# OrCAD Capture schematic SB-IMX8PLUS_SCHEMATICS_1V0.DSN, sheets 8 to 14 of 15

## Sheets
8 08. LVDS LCD: size A3; title: SB-iMX8PLUS   08. LVDS LCD
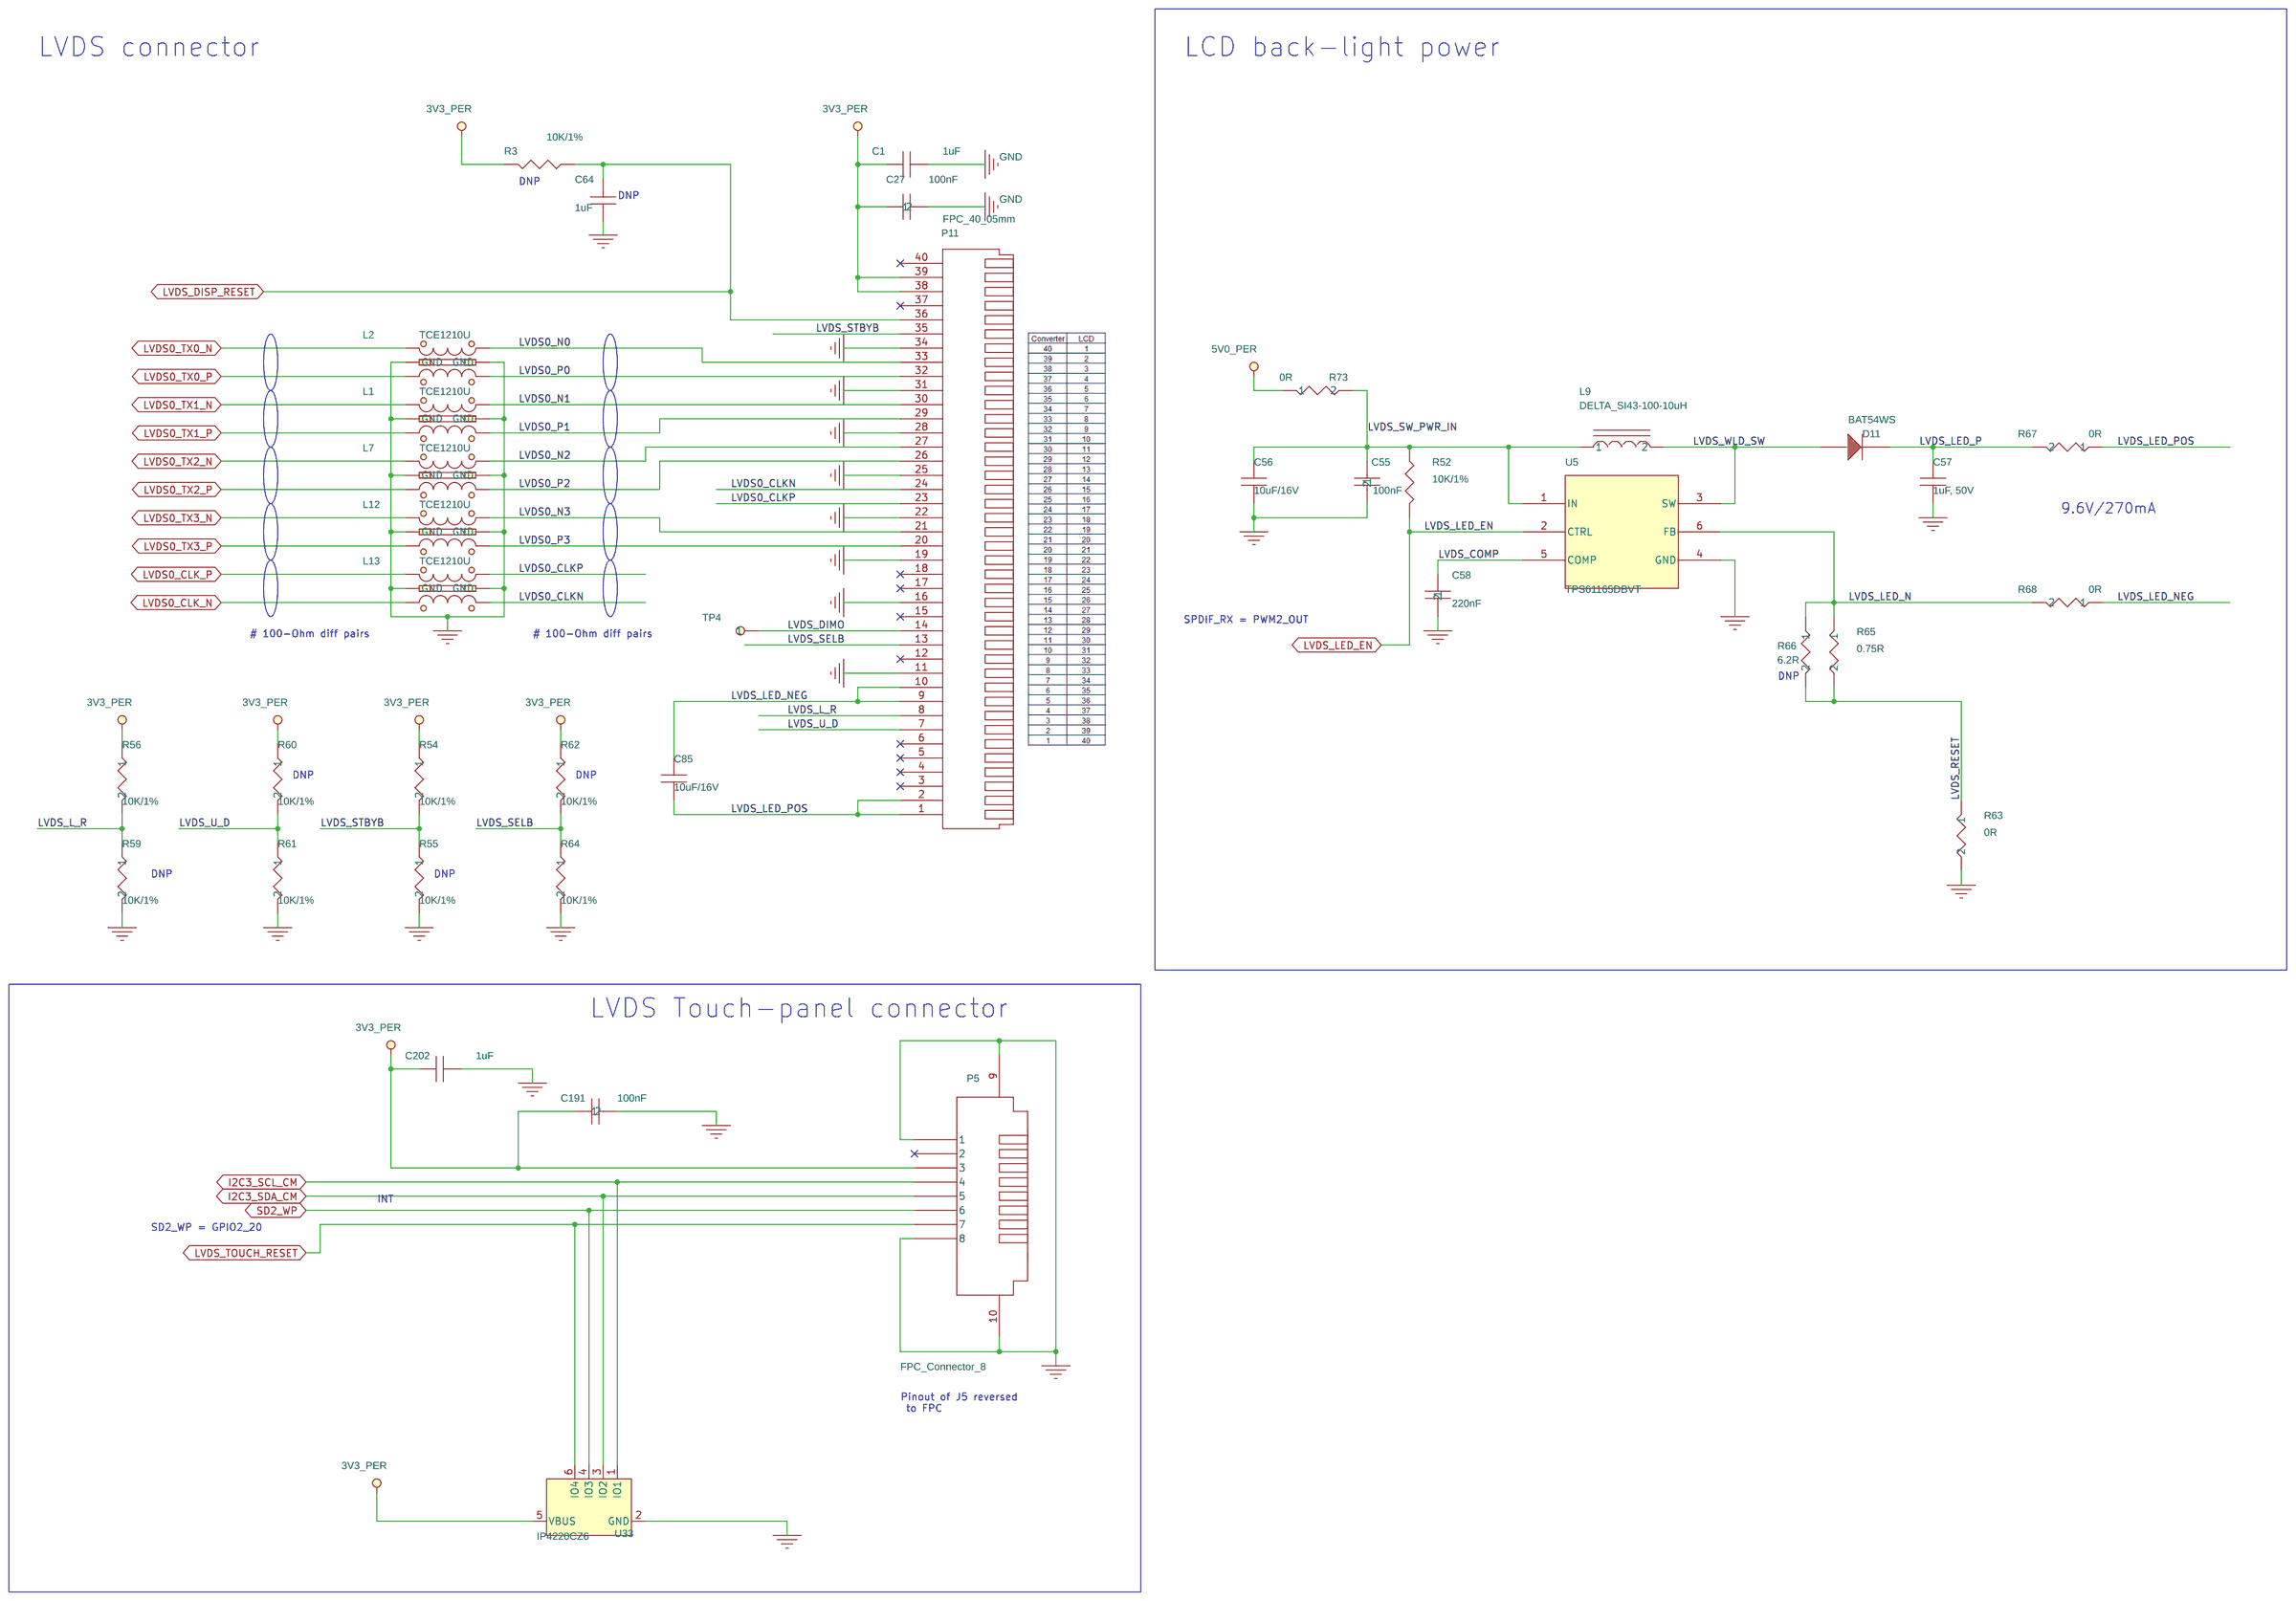
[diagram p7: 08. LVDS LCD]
9 09. HDMI, eARC: size B; title: SB-iMX8PLUS   09. HDMI, eARC
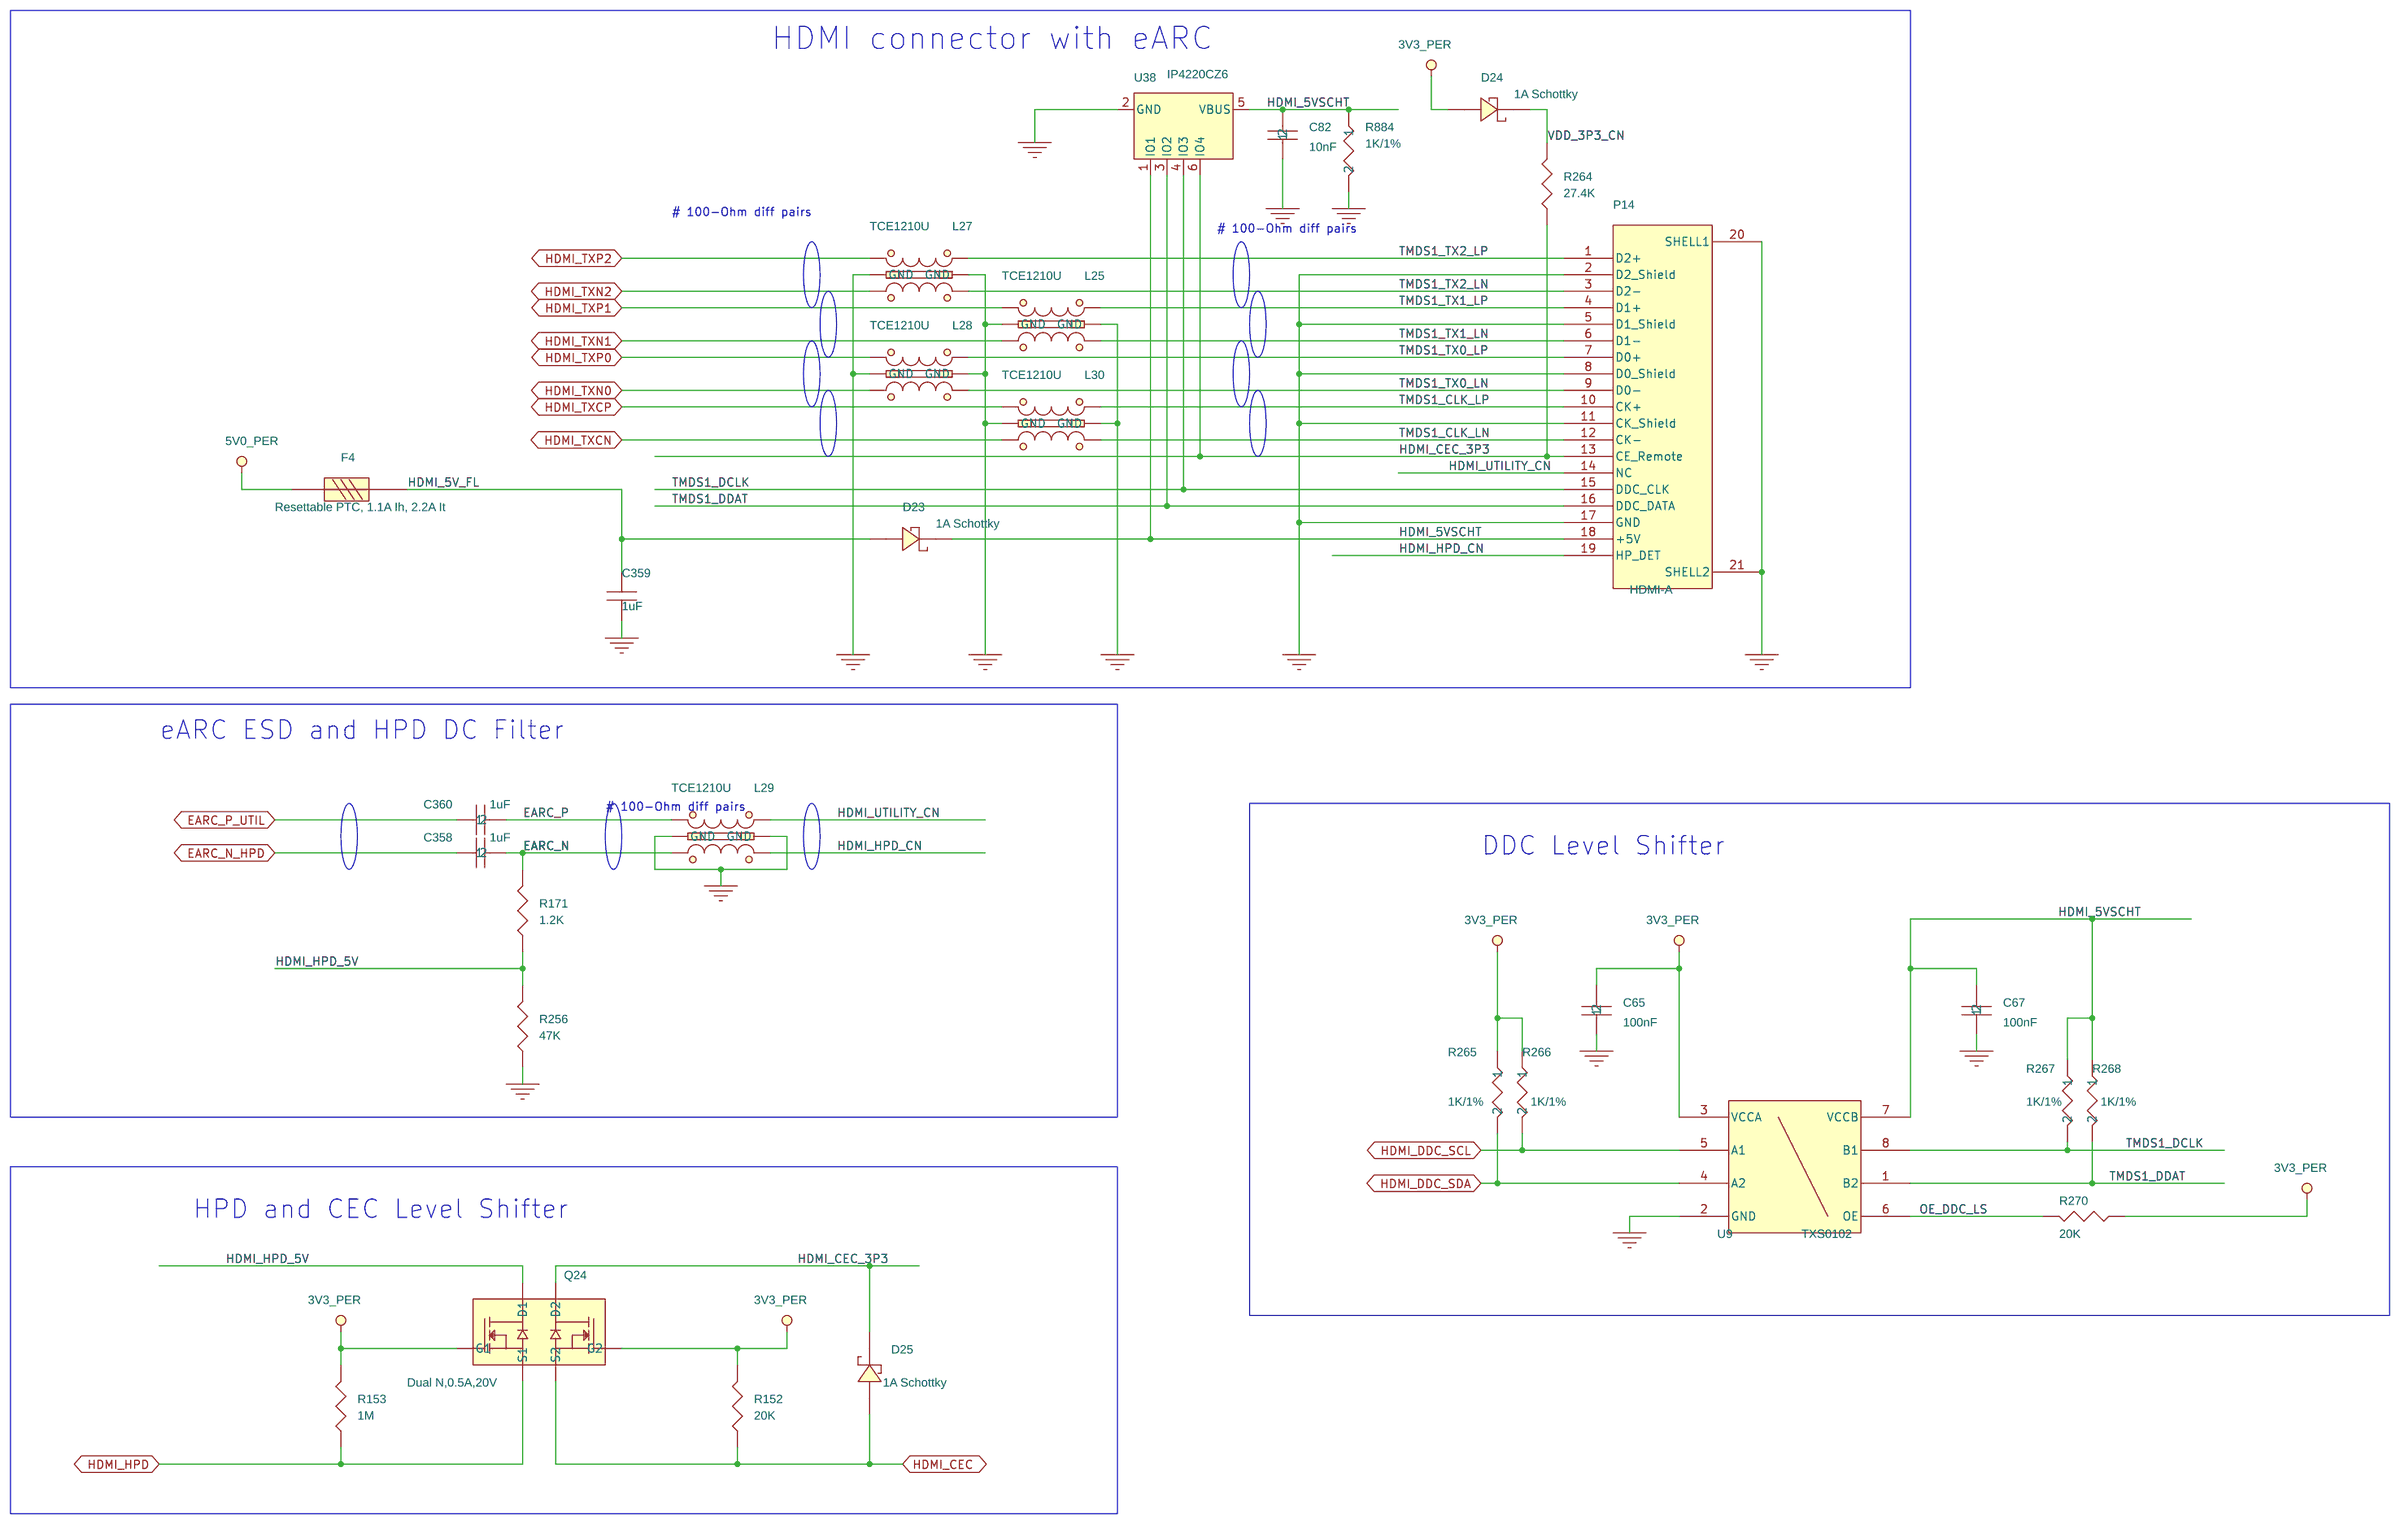
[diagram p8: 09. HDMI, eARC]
10 10. MIPI-CSI1 Connectors_A: size A3; title: SB-iMX8PLUS    10. MIPI-CSI1 Connectors
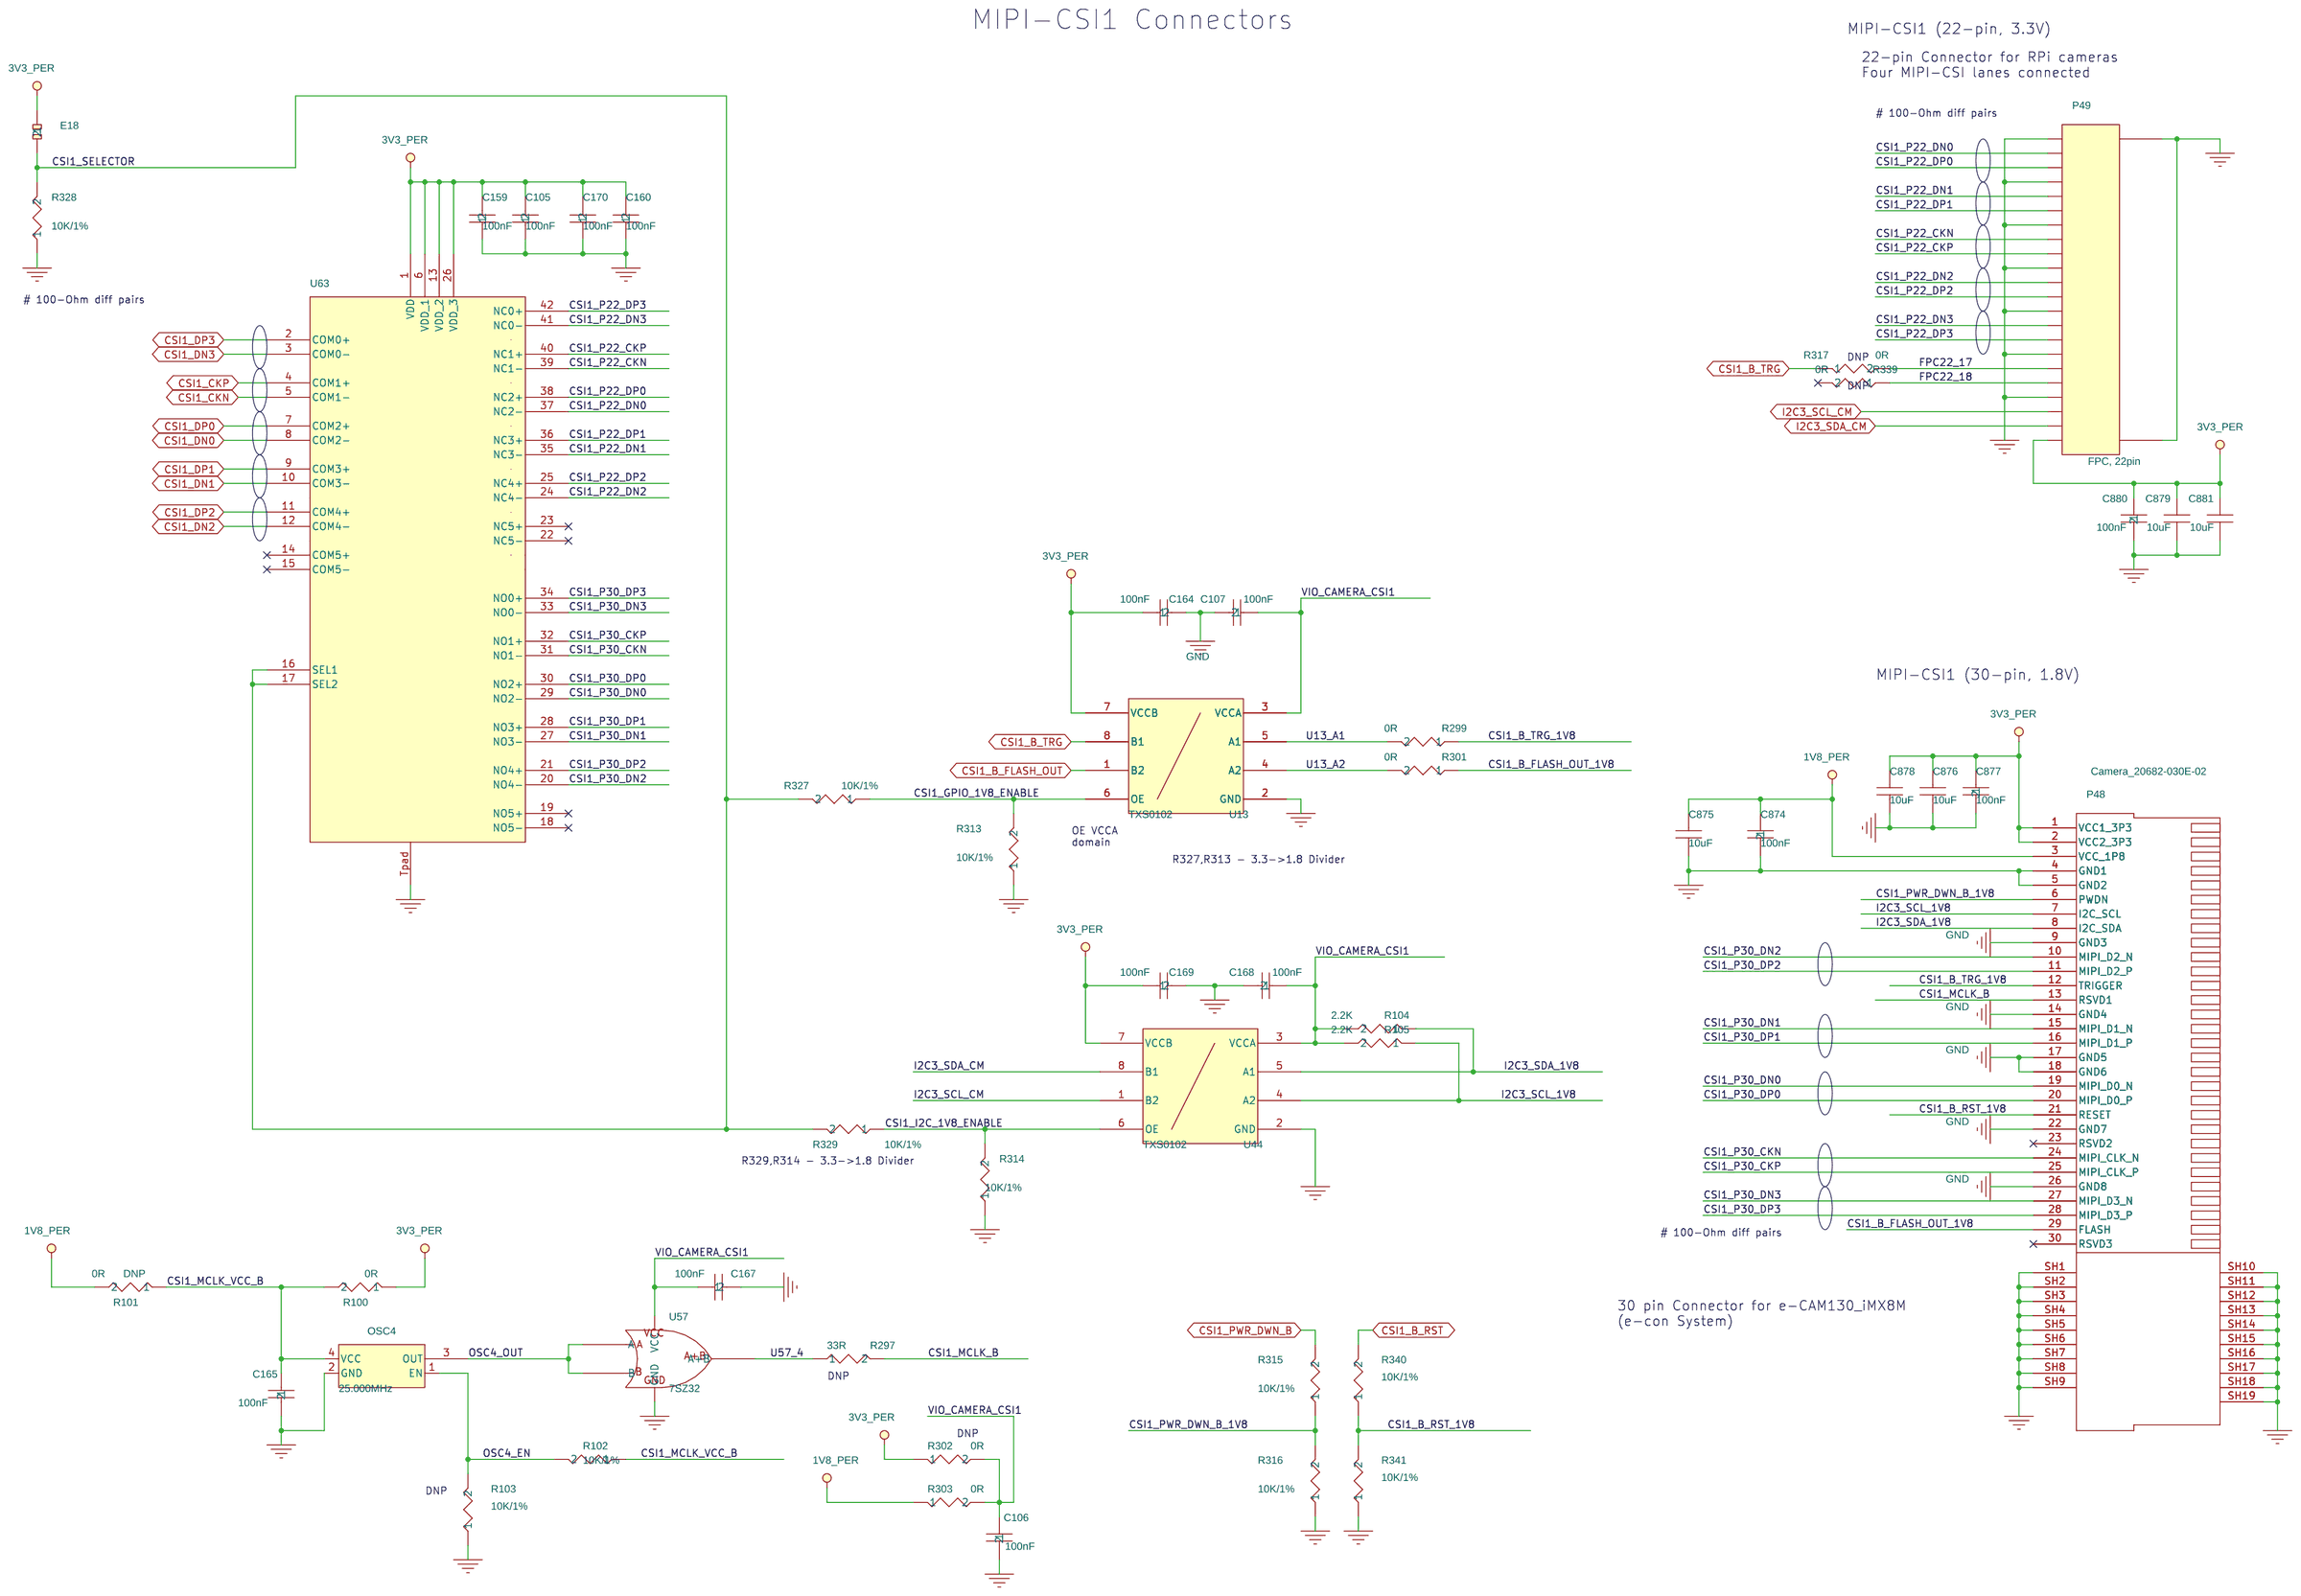
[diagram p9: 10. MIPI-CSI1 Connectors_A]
11 11. MIPI-CSI2 Connectors_B: size A3; title: SB-iMX8PLUS    11. MIPI-CSI2 Connectors
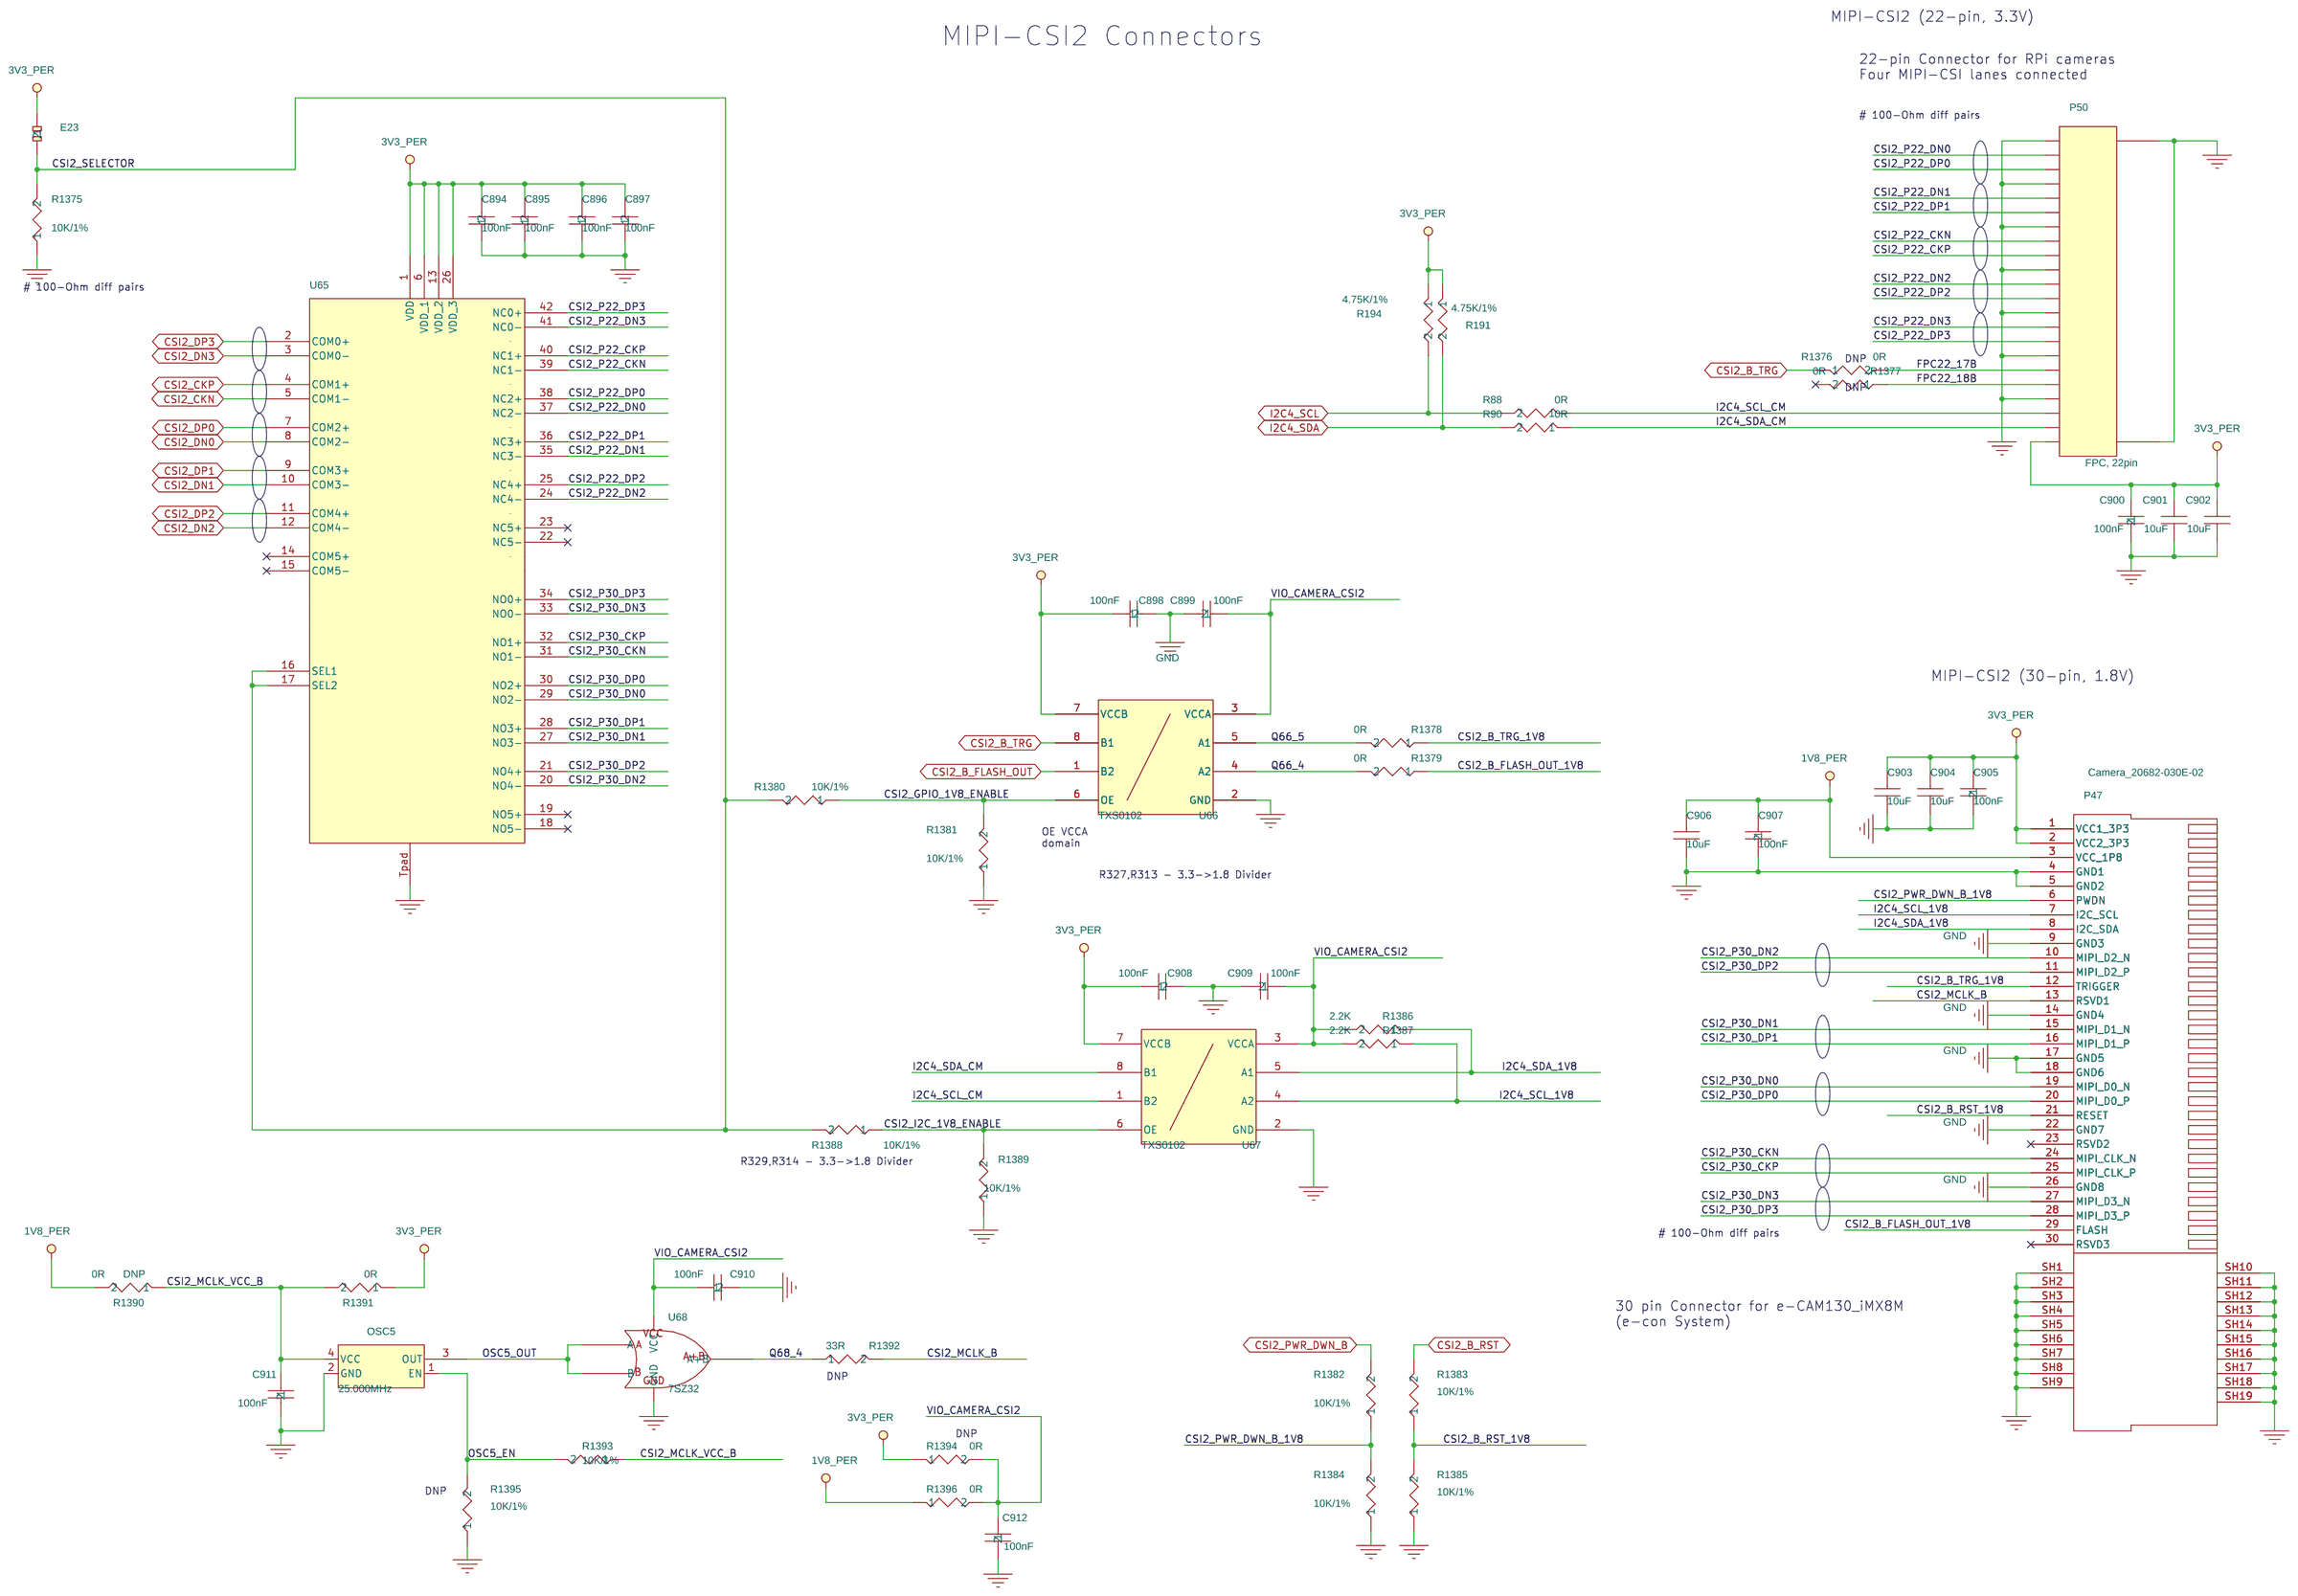
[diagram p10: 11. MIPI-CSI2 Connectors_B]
12 12. PCIe: size B; title: SB-iMX8PLUS    12. PCIe
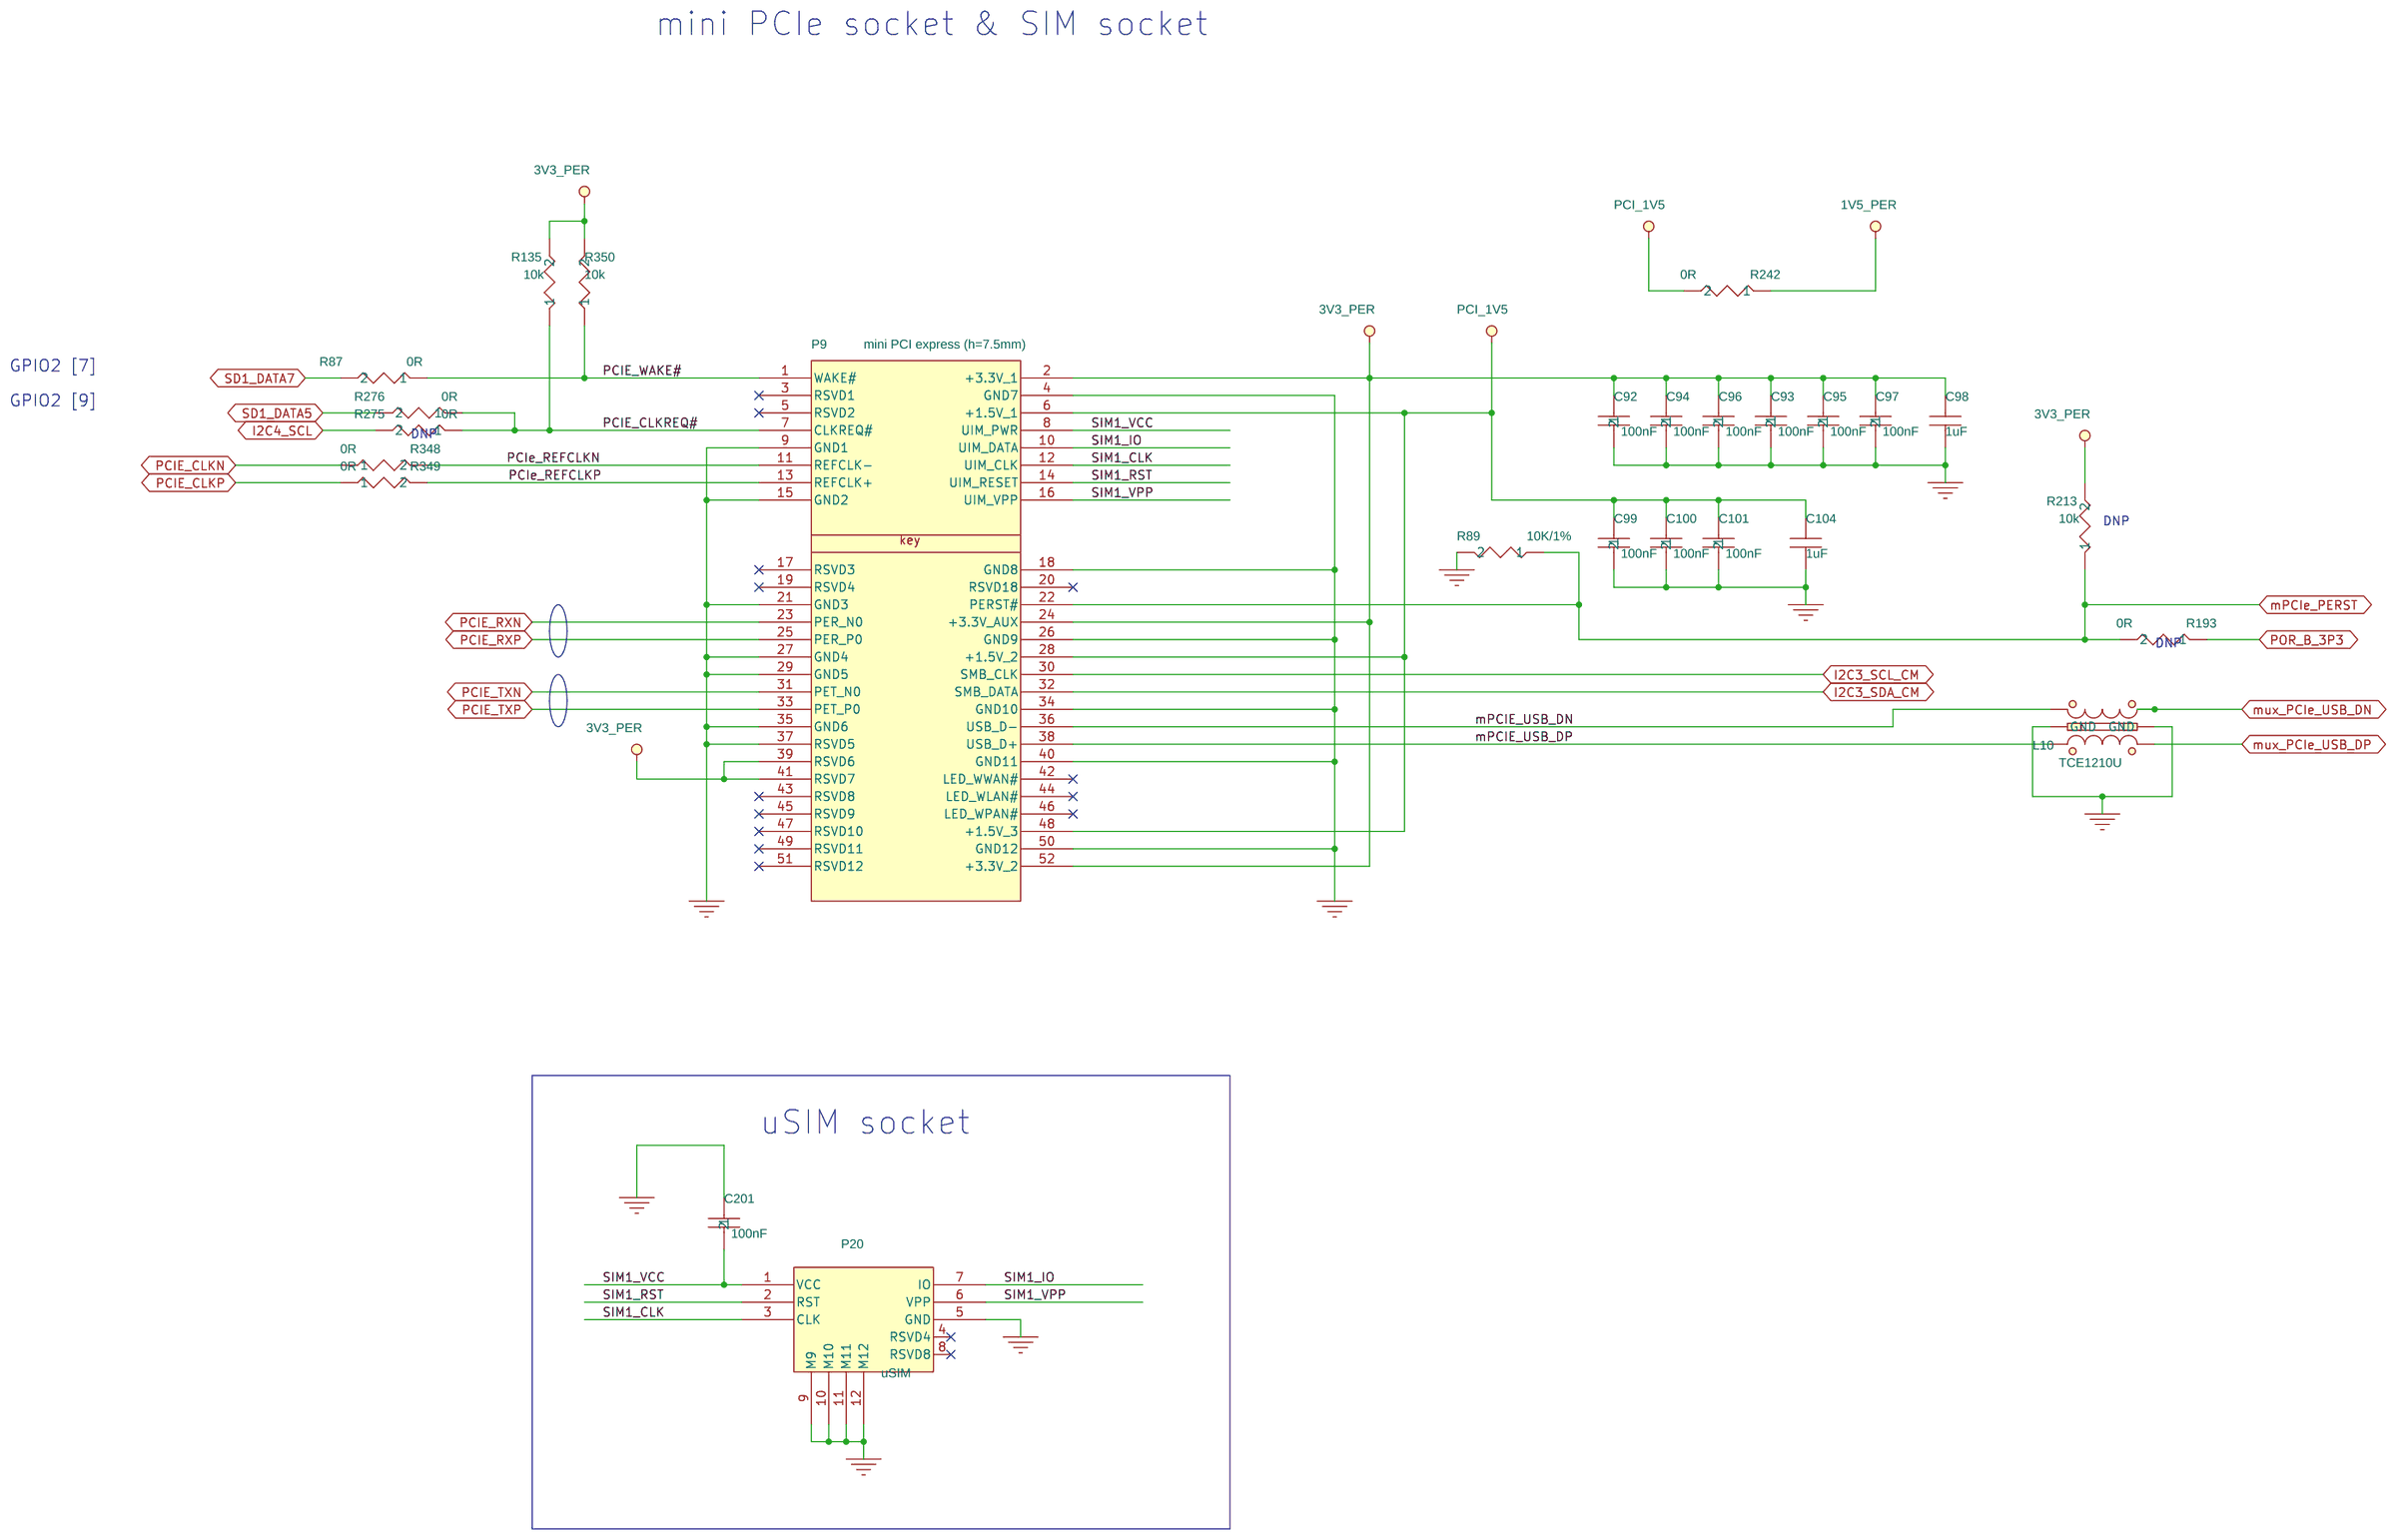
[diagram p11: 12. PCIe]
13 13. Power: size A3; title: SB-iMX8PLUS    13. POWER
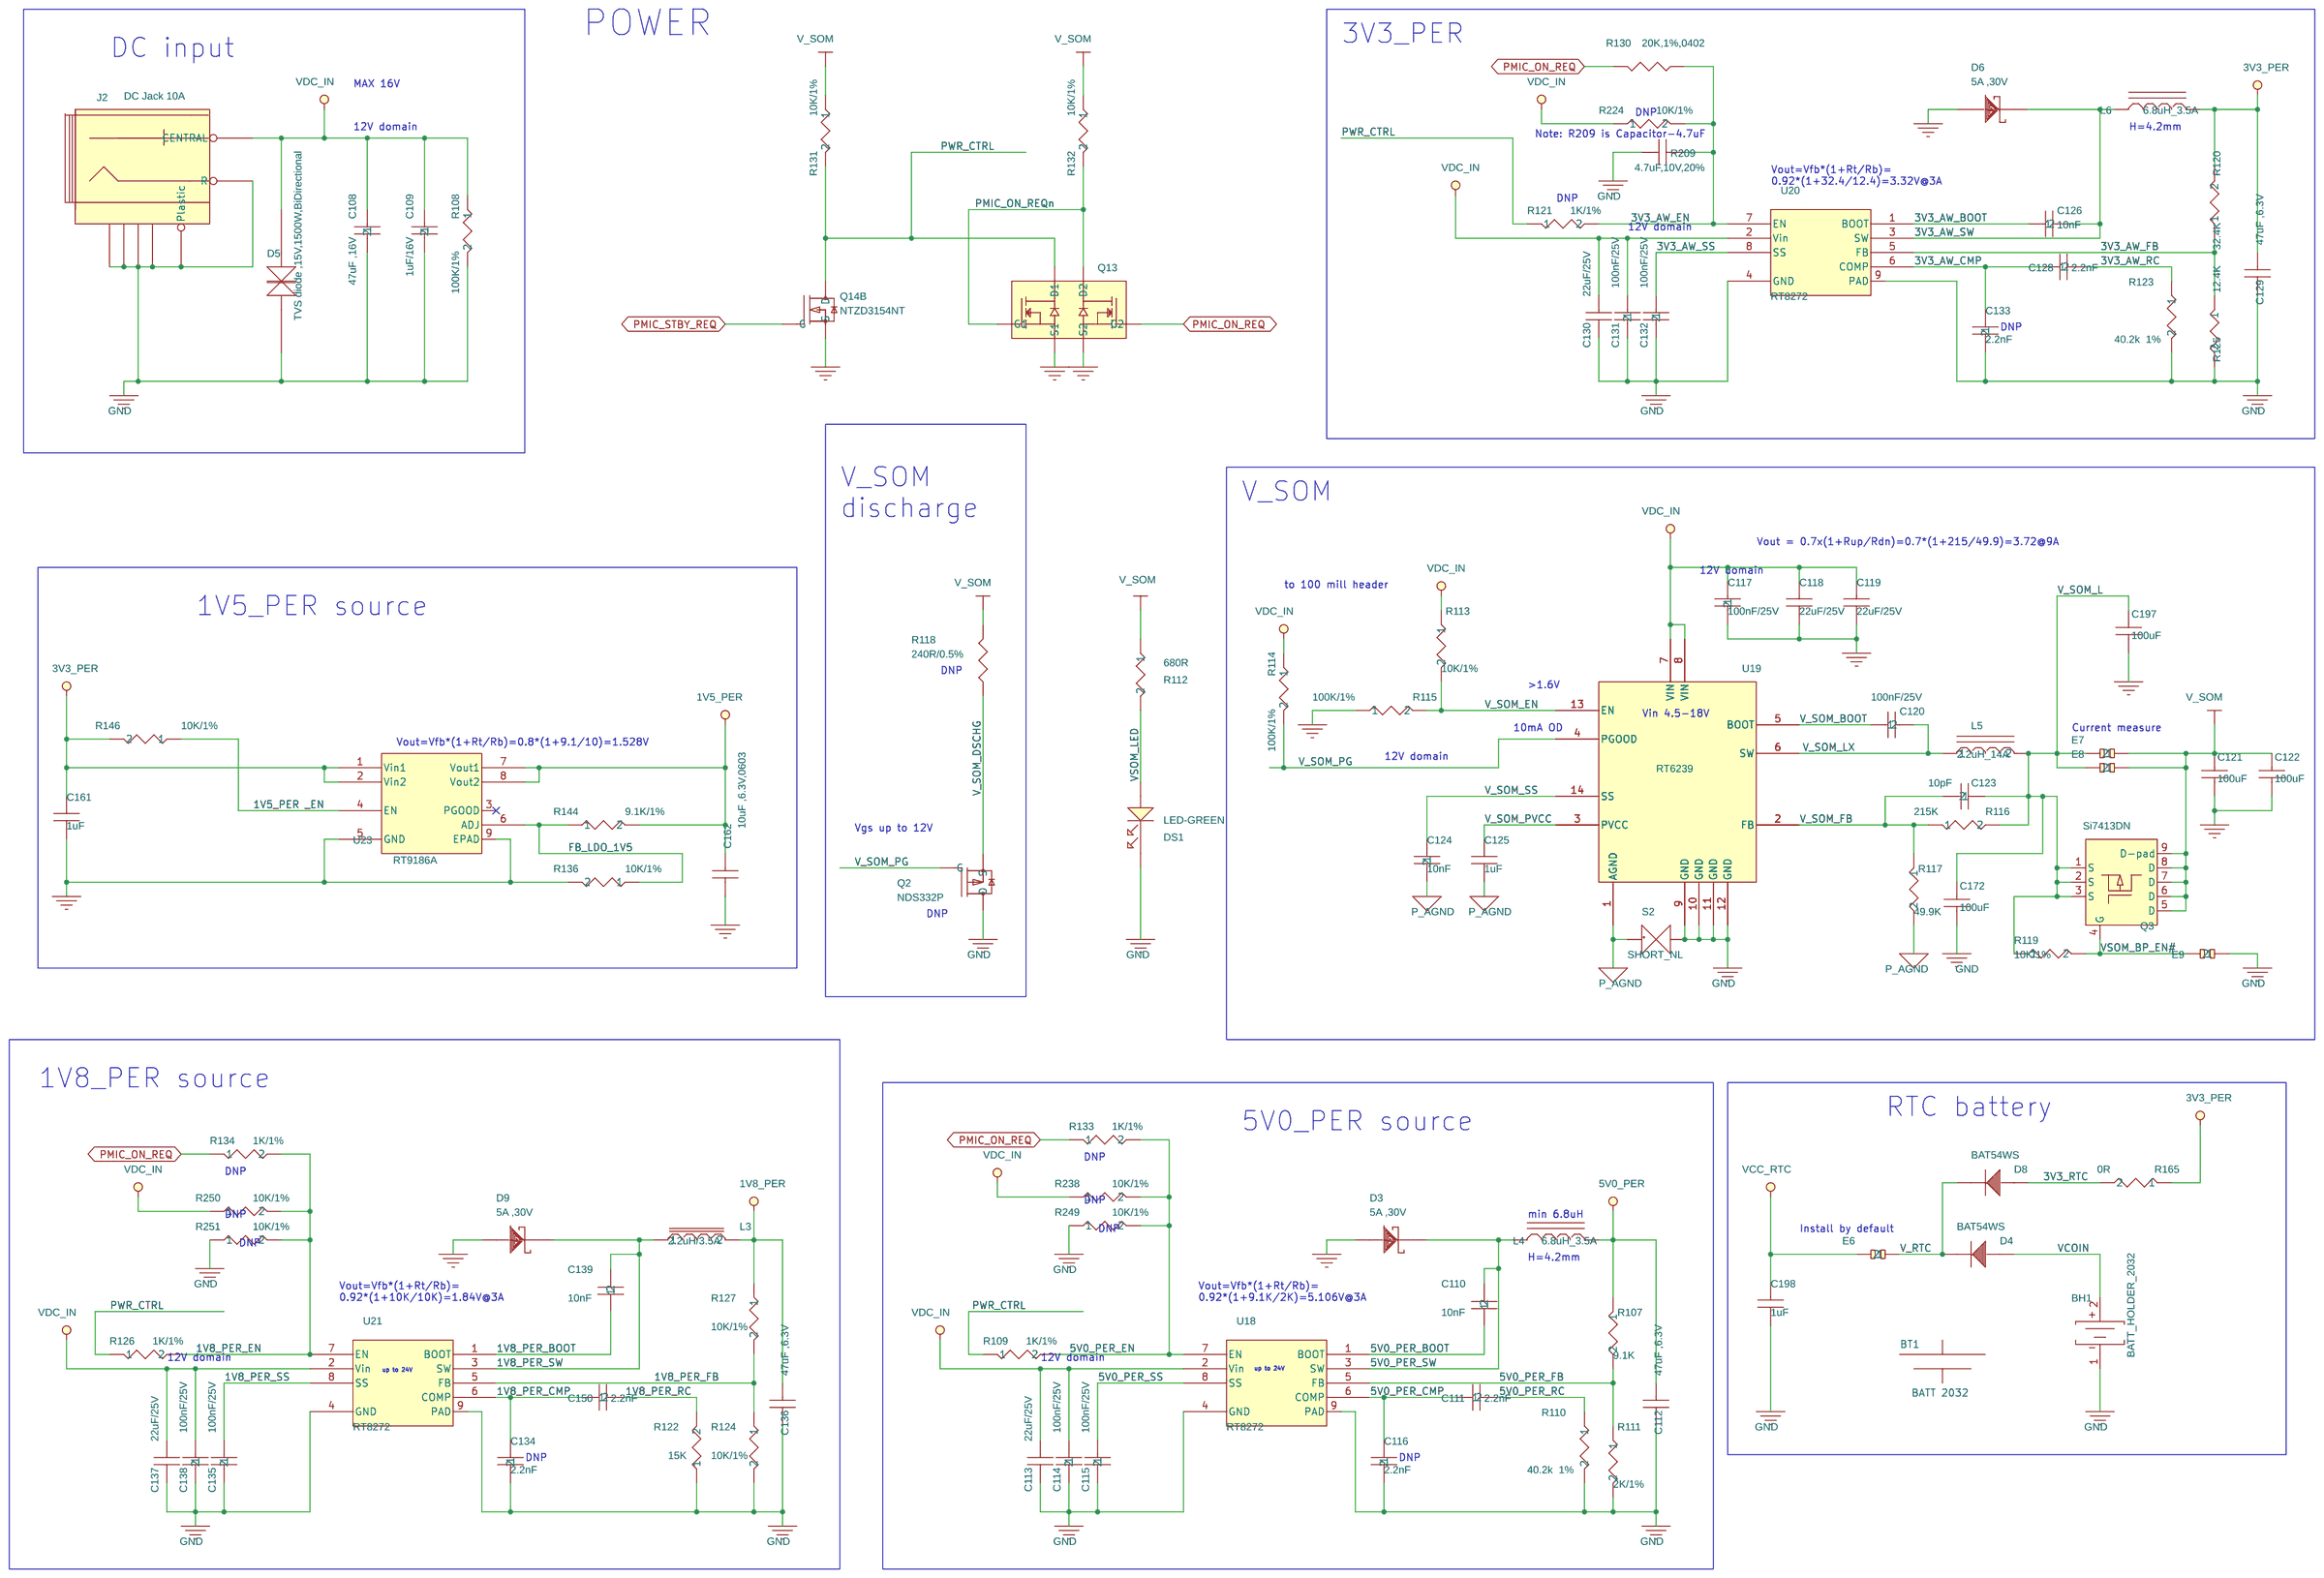
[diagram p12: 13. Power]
14 14. UART, RS232, SD, EEPROM: size A2; title: SB-iMX8PLUS      14. UART, RS232, SD Slot, EEPROM,GPIO
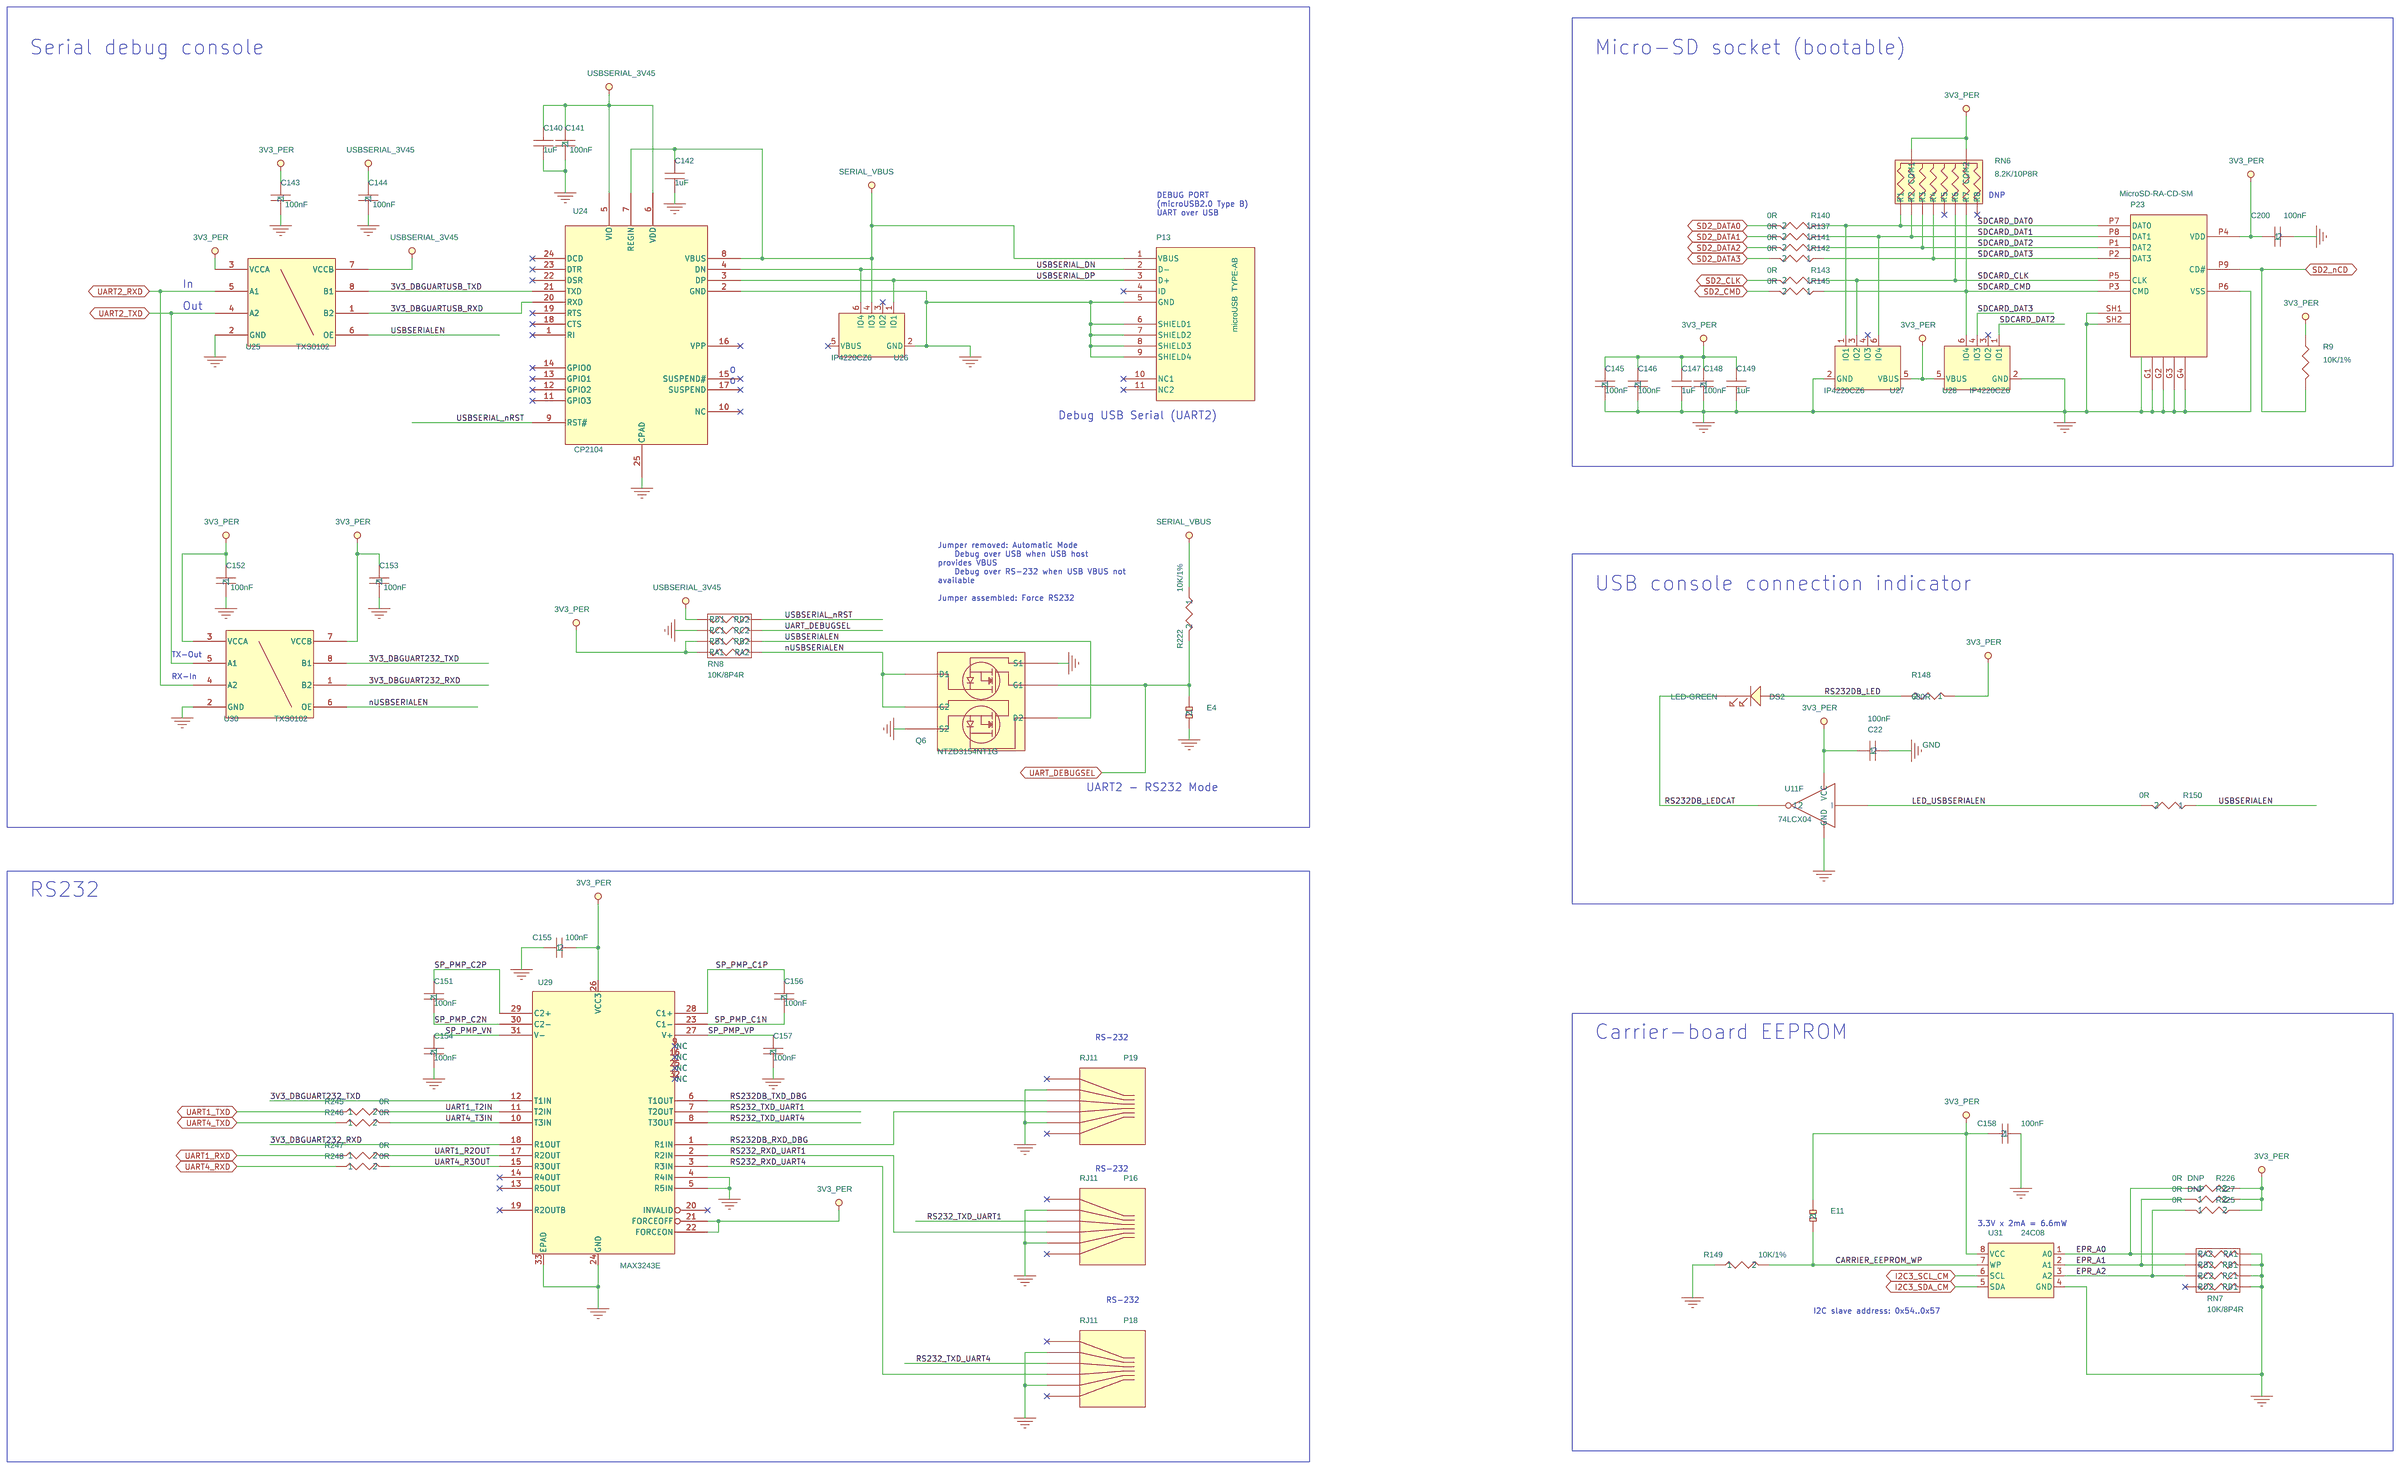
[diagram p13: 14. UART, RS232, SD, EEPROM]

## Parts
sheet 06. JTAG, CAN, GPIO Exp., Misc.
Q14  NTZD3154NT  [SOT-563-6]  (sections A,B)
sheet 08. LVDS LCD
C1  1uF  [RC0402]
C27  100nF  [RC0402]
C55  100nF  [RC0402]
C56  10uF/16V  [RC0603]
C57  1uF, 50V  [RC0603]
C58  220nF  [RC0402]
C64  1uF  [RC0402]
C85  10uF/16V  [RC0603]
C191  100nF  [RC0402]
C202  1uF  [RC0402]
D11  BAT54WS  [SOD-323]
L1  TCE1210U  [EMI1012-ESD]
L2  TCE1210U  [EMI1012-ESD]
L7  TCE1210U  [EMI1012-ESD]
L9  DELTA_SI43-100-10uH  [IND4x4x2_5]
L12  TCE1210U  [EMI1012-ESD]
L13  TCE1210U  [EMI1012-ESD]
P5  FPC_Connector_8  [FPC_8]
P11  FPC_40_05mm  [FPC05SM40-1]
R3  10K/1%  [RC0402]
R52  10K/1%  [RC0402]
R54  10K/1%  [RC0402]
R55  10K/1%  [RC0402]
R56  10K/1%  [RC0402]
R59  10K/1%  [RC0402]
R60  10K/1%  [RC0402]
R61  10K/1%  [RC0402]
R62  10K/1%  [RC0402]
R63  0R  [RC0402]
R64  10K/1%  [RC0402]
R65  0.75R  [RC0402]
R66  6.2R  [RC0402]
R67  0R  [RC1206]
R68  0R  [RC1206]
R73  0R  [RC1206]
TP4  TESTPOINT  [TESTPOINT]
U5  TPS61165DBVT  [SOT23-6]
U33  IP4220CZ6  [SOT23-6L]
sheet 09. HDMI, eARC
C65  100nF  [RC0402]
C67  100nF  [RC0402]
C82  10nF  [RC0402]
C358  1uF  [RC0402]
C359  1uF  [RC0402]
C360  1uF  [RC0402]
D23  1A Schottky  [SOD-123]
D24  1A Schottky  [SOD-123]
D25  1A Schottky  [SOD-123]
F4  Resettable PTC, 1.1A Ih, 2.2A It  [FUSE-1206]
L25  TCE1210U  [EMI1012-ESD]
L27  TCE1210U  [EMI1012-ESD]
L28  TCE1210U  [EMI1012-ESD]
L29  TCE1210U  [EMI1012-ESD]
L30  TCE1210U  [EMI1012-ESD]
P14  HDMI-A  [SMT(HDMI-A)]
Q24  Dual N,0.5A,20V  [SOT-563-6]
R152  20K  [RC0402]
R153  1M  [RC0402]
R171  1.2K  [RC0402]
R256  47K  [RC0402]
R264  27.4K  [RC0402]
R265  1K/1%  [RC0402]
R266  1K/1%  [RC0402]
R267  1K/1%  [RC0402]
R268  1K/1%  [RC0402]
R270  20K  [RC0402]
R884  1K/1%  [RC0402]
U9  TXS0102  [MO-187DA-8]
U38  IP4220CZ6  [SOT23-6L]
sheet 10. MIPI-CSI1 Connectors_A
C105  100nF  [RC0402]
C106  100nF  [RC0402]
C107  100nF  [RC0402]
C159  100nF  [RC0402]
C160  100nF  [RC0402]
C164  100nF  [RC0402]
C165  100nF  [RC0402]
C167  100nF  [RC0402]
C168  100nF  [RC0402]
C169  100nF  [RC0402]
C170  100nF  [RC0402]
C874  100nF  [RC0402]
C875  10uF  [RC0603]
C876  10uF  [RC0603]
C877  100nF  [RC0402]
C878  10uF  [RC0603]
C879  10uF  [RC0603]
C880  100nF  [RC0402]
C881  10uF  [RC0603]
E18  HDR1X2  [1X2THHDR]
OSC4  25.000MHz  [OSC3225]
P48  Camera_20682-030E-02  [CON30]
P49  FPC, 22pin  [FPC05SM22]
R100  0R  [RC0402]
R101  0R  [RC0402]
R102  10K/1%  [RC0402]
R103  10K/1%  [RC0402]
R104  2.2K  [RC0402]
R105  2.2K  [RC0402]
R297  33R  [RC0402]
R299  0R  [RC0402]
R301  0R  [RC0402]
R302  0R  [RC0402]
R303  0R  [RC0402]
R313  10K/1%  [RC0402]
R314  10K/1%  [RC0402]
R315  10K/1%  [RC0402]
R316  10K/1%  [RC0402]
R317  0R  [RC0402]
R327  10K/1%  [RC0402]
R328  10K/1%  [RC0402]
R329  10K/1%  [RC0402]
R339  0R  [RC0402]
R340  10K/1%  [RC0402]
R341  10K/1%  [RC0402]
U13  TXS0102  [MO-187DA-8]
U44  TXS0102  [MO-187DA-8]
U57  7SZ32  [SC70]
U63  Value  [21-0181B_T423590M-1_MXM]
sheet 11. MIPI-CSI2 Connectors_B
C894  100nF  [RC0402]
C895  100nF  [RC0402]
C896  100nF  [RC0402]
C897  100nF  [RC0402]
C898  100nF  [RC0402]
C899  100nF  [RC0402]
C900  100nF  [RC0402]
C901  10uF  [RC0603]
C902  10uF  [RC0603]
C903  10uF  [RC0603]
C904  10uF  [RC0603]
C905  100nF  [RC0402]
C906  10uF  [RC0603]
C907  100nF  [RC0402]
C908  100nF  [RC0402]
C909  100nF  [RC0402]
C910  100nF  [RC0402]
C911  100nF  [RC0402]
C912  100nF  [RC0402]
E23  HDR1X2  [1X2THHDR]
OSC5  25.000MHz  [OSC3225]
P47  Camera_20682-030E-02  [CON30]
P50  FPC, 22pin  [FPC05SM22]
R88  0R  [RC0402]
R90  0R  [RC0402]
R191  4.75K/1%  [RC0402]
R194  4.75K/1%  [RC0402]
R1375  10K/1%  [RC0402]
R1376  0R  [RC0402]
R1377  0R  [RC0402]
R1378  0R  [RC0402]
R1379  0R  [RC0402]
R1380  10K/1%  [RC0402]
R1381  10K/1%  [RC0402]
R1382  10K/1%  [RC0402]
R1383  10K/1%  [RC0402]
R1384  10K/1%  [RC0402]
R1385  10K/1%  [RC0402]
R1386  2.2K  [RC0402]
R1387  2.2K  [RC0402]
R1388  10K/1%  [RC0402]
R1389  10K/1%  [RC0402]
R1390  0R  [RC0402]
R1391  0R  [RC0402]
R1392  33R  [RC0402]
R1393  10K/1%  [RC0402]
R1394  0R  [RC0402]
R1395  10K/1%  [RC0402]
R1396  0R  [RC0402]
U65  Value  [21-0181B_T423590M-1_MXM]
U66  TXS0102  [MO-187DA-8]
U67  TXS0102  [MO-187DA-8]
U68  7SZ32  [SC70]
sheet 12. PCIe
C92  100nF  [RC0402]
C93  100nF  [RC0402]
C94  100nF  [RC0402]
C95  100nF  [RC0402]
C96  100nF  [RC0402]
C97  100nF  [RC0402]
C98  1uF  [RC0402]
C99  100nF  [RC0402]
C100  100nF  [RC0402]
C101  100nF  [RC0402]
C104  1uF  [RC0402]
C201  100nF  [RC0402]
L10  TCE1210U  [EMI1012-ESD]
P9  mini PCI express (h=7.5mm)  [MINIPCIE-4]
P20  uSIM  [SKT-MicroSIM6-SM]
R87  0R  [RC0402]
R89  10K/1%  [RC0402]
R135  10k  [RC0402]
R193  0R  [RC0402]
R213  10k  [RC0402]
R242  0R  [RC0402]
R275  0R  [RC0402]
R276  0R  [RC0402]
R348  0R  [RC0402]
R349  0R  [RC0402]
R350  10k  [RC0402]
sheet 13. Power
BH1  BATT_HOLDER_2032  [BATTH20MM]
BT1  BATT 2032
C108  47uF ,16V  [C1210H2_5]
C109  1uF/16V  [RC0805]
C110  10nF  [RC0402]
C111  2.2nF  [RC0402]
C112  47uF ,6.3V  [C0805]
C113  22uF/25V  [C0805]
C114  100nF/25V  [RC0402]
C115  100nF/25V  [RC0402]
C116  2.2nF  [RC0402]
C117  100nF/25V  [RC0402]
C118  22uF/25V  [C0805]
C119  22uF/25V  [C0805]
C120  100nF/25V  [RC0402]
C121  100uF  [C1210H2_5]
C122  100uF  [C1210H2_5]
C123  10pF  [RC0402]
C124  10nF  [RC0402]
C125  1uF  [RC0402]
C126  10nF  [RC0402]
C128  2.2nF  [RC0402]
C129  47uF ,6.3V  [C0805]
C130  22uF/25V  [C0805]
C131  100nF/25V  [RC0402]
C132  100nF/25V  [RC0402]
C133  2.2nF  [RC0402]
C134  2.2nF  [RC0402]
C135  100nF/25V  [RC0402]
C136  47uF ,6.3V  [C0805]
C137  22uF/25V  [C0805]
C138  100nF/25V  [RC0402]
C139  10nF  [RC0402]
C150  2.2nF  [RC0402]
C161  1uF  [RC0402]
C162  10uF ,6.3V,0603  [C0603-08]
C172  100uF  [C1210H2_5]
C197  100uF  [C1210H2_5]
C198  1uF  [RC0402]
D3  5A ,30V  [SOD-128]
D4  BAT54WS  [SOD-323]
D5  TVS diode ,15V,1500W,BiDirectional  [DO-214AB]
D6  5A ,30V  [SOD-128]
D8  BAT54WS  [SOD-323]
D9  5A ,30V  [SOD-128]
DS1  LED-GREEN  [LED-1206]
E6  HDR1X2  [1X2THHDR]
E7  HDR1X2  [1X2THHDR]
E8  HDR1X2  [1X2THHDR]
E9  HDR1X2  [1X2THHDR]
J2  DC Jack 10A  [PJ-0810-TH]
L3  2.2uH/3.5A  [IND4_3x4_7SM]
L4  6.8uH_3.5A  [IND8_2x8_2]
L5  2.2uH_14A  [IND7x7_2SM]
L6  6.8uH_3.5A  [IND8_2x8_2]
Q2  NDS332P  [SOT23]
Q3  Si7413DN  [Powerpak1212-8]
Q13  0.5A,20V,Vgs max 6V  [SOT-563-6]
R107  9.1K  [RC0402]
R108  100K/1%  [RC0402]
R109  1K/1%  [RC0402]
R110  40.2k  1%  [RC0402]
R111  2K/1%  [RC0402]
R112  680R  [RC0402]
R113  10K/1%  [RC0402]
R114  100K/1%  [RC0402]
R115  100K/1%  [RC0402]
R116  215K  [RC0402]
R117  49.9K  [RC0402]
R118  240R/0.5%  [RC0402]
R119  10K/1%  [RC0402]
R120  32.4K  [RC0402]
R121  1K/1%  [RC0402]
R122  15K  [RC0402]
R123  40.2k  1%  [RC0402]
R124  10K/1%  [RC0402]
R125  12.4K  [RC0402]
R126  1K/1%  [RC0402]
R127  10K/1%  [RC0402]
R130  20K,1%,0402  [RC0402]
R131  10K/1%  [RC0402]
R132  10K/1%  [RC0402]
R133  1K/1%  [RC0402]
R134  1K/1%  [RC0402]
R136  10K/1%  [RC0402]
R144  9.1K/1%  [RC0402]
R146  10K/1%  [RC0402]
R165  0R  [RC0402]
R209  4.7uF,10V,20%  [RC0402]
R224  10K/1%  [RC0402]
R238  10K/1%  [RC0402]
R249  10K/1%  [RC0402]
R250  10K/1%  [RC0402]
R251  10K/1%  [RC0402]
S2  SHORT_NL  [SHORT_NL]
U18  RT8272  [PSOP-8-2X2]
U19  RT6239  [uQFN2x3-14]
U20  RT8272  [PSOP-8-2X2]
U21  RT8272  [PSOP-8-2X2]
U23  RT9186A  [DFN3x3-8]
sheet 14. UART, RS232, SD, EEPROM
C22  100nF  [RC0402]
C140  1uF  [RC0402]
C141  100nF  [RC0402]
C142  1uF  [RC0402]
C143  100nF  [RC0402]
C144  100nF  [RC0402]
C145  100nF  [RC0402]
C146  100nF  [RC0402]
C147  1uF  [RC0402]
C148  100nF  [RC0402]
C149  1uF  [RC0402]
C151  100nF  [RC0402]
C152  100nF  [RC0402]
C153  100nF  [RC0402]
C154  100nF  [RC0402]
C155  100nF  [RC0402]
C156  100nF  [RC0402]
C157  100nF  [RC0402]
C158  100nF  [RC0402]
C200  100nF  [RC0402]
DS2  LED-GREEN  [LED-1206]
E4  HDR1X2  [1X2THHDR]
E11  HDR1X2  [1X2THHDR]
P13  microUSB  TYPE-AB  [MICRO-USB-AB-RA-SM]
P16  RJ11  [RJ11TH6-6]
P18  RJ11  [RJ11TH6-6]
P19  RJ11  [RJ11TH6-6]
P23  MicroSD-RA-CD-SM  [MicroSD-RA-CD-SM]
Q6  NTZD3154NT1G  [SOT-563]
R9  10K/1%  [RC0402]
R137  0R  [RC0402]
R140  0R  [RC0402]
R141  0R  [RC0402]
R142  0R  [RC0402]
R143  0R  [RC0402]
R145  0R  [RC0402]
R148  680R  [RC0402]
R149  10K/1%  [RC0402]
R150  0R  [RC0402]
R222  10K/1%  [RC0402]
R225  0R  [RC0402]
R226  0R  [RC0402]
R227  0R  [RC0402]
R245  0R  [RC0402]
R246  0R  [RC0402]
R247  0R  [RC0402]
R248  0R  [RC0402]
RN6  8.2K/10P8R  [RESNET10P1206]
RN7  10K/8P4R  [RESNET8P0805]
RN8  10K/8P4R  [RESNET8P0805]
U11  74LCX04  [TSSOP-14]  (sections A,B,F)
U24  CP2104  [MO-220VGGD-8]
U25  TXS0102  [MO-187DA-8]
U26  IP4220CZ6  [SOT23-6L]
U27  IP4220CZ6  [SOT23-6L]
U28  IP4220CZ6  [SOT23-6L]
U29  MAX3243E  [QFN5x5-32]
U30  TXS0102  [MO-187DA-8]
U31  24C08  [MO-229VCED-2]

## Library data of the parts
Q14 = N-MOSFET_Dual: CLABCONF0: = SB-iMX8PLUS; P/N: 131D31540S
C1 C98 C104 C140 C142 C147 C149 C161 C198 C202 = 1uF,X5R,6.3V,0402: CLABCONF0: = SB-iMX8PLUS
C27 C96 C151 C874 C910 = 100nF,_10V,_X7R,_10%,_0402: CLABCONF0: = SB-iMX8PLUS
C55 C67 C92 C145 C168 C911 = 100nF,_10V,_X7R,_10%,_0402_3: CLABCONF0: = SB-iMX8PLUS
C56 = 10uF,6.3V,0603,20%X5R_1: CLABCONF0: = SB-iMX8PLUS
C57 = 1uF,X5R,6.3V,0402: CLABCONF0: = SB-iMX8PLUS; P/N: 151D10510S
C58 = 100nF,_10V,_X7R,_10%,_0402_2: CLABCONF0: = SB-iMX8PLUS; P/N: 151C22400S
C64 = 1uF,X5R,6.3V,0402: CLABCONF0: DNP
C85 = 10uF,6.3V,0603,20%X5R: CLABCONF0: = SB-iMX8PLUS
C170 C191 C200 C201 C895 = 100nF,_10V,_X7R,_10%,_0402_1: CLABCONF0: = SB-iMX8PLUS
D4 D8 D11 = BAT54WS_0: CLABCONF0: = SB-iMX8PLUS
L1 L2 L7 L10 L12 L13 L25 L27-L30 = ESD_CHOKE_DIFFx2_10: CLABCONF0: = SB-iMX8PLUS; P/N: 142D11801S
L9 = INC_DELTA_SI43-100,_10uH: CLABCONF0: = SB-iMX8PLUS; CLABCONF1: <null>
P5 = FPC_Connector_6: CLABCONF0: = SB-iMX8PLUS; P/N: 182P00803S
P11 = FPC_40_05mm: CLABCONF0: = SB-iMX8PLUS; P/N: 182P04001S
R3 = 10K,1%,0402,1_16W_0_1: CLABCONF0: DNP
R9 R52 = 10K,1%,0402,1_16W_0: CLABCONF0: = SB-iMX8PLUS
R54 R328 R1375 = 10K,1%,0402,1_16W_3: CLABCONF0: = SB-iMX8PLUS
R55 = 10K,1%,0402,1_16W_5: CLABCONF0: DNP
R56 R327 R1382 = 10K,1%,0402,1_16W_6: CLABCONF0: = SB-iMX8PLUS
R59 = 10K,1%,0402,1_16W_7: CLABCONF0: DNP
R60 R103 = 10K,1%,0402,1_16W: CLABCONF0: DNP
R61 R222 R340 R1383 = 10K,1%,0402,1_16W_1: CLABCONF0: = SB-iMX8PLUS
R62 = 10K,1%,0402,1_16W_2: CLABCONF0: DNP
R63 = 2.2R,5%,0402,1_16W_1: CLABCONF0: = SB-iMX8PLUS; P/N: 161C00005S
R64 R146 R341 R1385 = 10K,1%,0402,1_16W_4: CLABCONF0: = SB-iMX8PLUS
R65 = 2.2R,5%,0402,1_16W_2: CLABCONF0: = SB-iMX8PLUS; P/N: 161C0R751S
R66 = 2.2R,5%,0402,1_16W: CLABCONF0: DNP; P/N: 161C06R25S
R67 = 0R,_1206: CLABCONF0: = SB-iMX8PLUS
R68 = 0R,_1206_1: CLABCONF0: = SB-iMX8PLUS
R73 = 0R,_1206_2: CLABCONF0: = SB-iMX8PLUS
TP4 = TESTPOINT: CLABCONF0: DNP
U5 = TPS61165DBVT: CLABCONF0: = SB-iMX8PLUS; P/N: 123C15100S
U26-U28 U33 U38 = IP4220CZ6_0: CLABCONF0: = SB-iMX8PLUS
C65 C97 C158 C159 C905 = 100nF,_10V,_X7R,_10%,_0402_2: CLABCONF0: = SB-iMX8PLUS
C82 C124 = 10nF,_25V,_X7R,_10%,_0402: CLABCONF0: = SB-iMX8PLUS
C358 = 100nF,_10V,_X7R,_10%,_0402: CLABCONF0: = SB-iMX8PLUS; P/N: 151C10500S
C359 = Cap_1uF,X5R,6.3V,0402: CLABCONF0: = SB-iMX8PLUS
C360 = 100nF,_10V,_X7R,_10%,_0402_1: CLABCONF0: = SB-iMX8PLUS; P/N: 151C10500S
D23-D25 = 1A_Schottky_Barrier_Rectifier: CLABCONF0: = SB-iMX8PLUS
F4 = Fuse,_0.75A_Ih,_1.5A_It: CLABCONF0: = SB-iMX8PLUS; P/N: 175P22200S
P14 = HDMI_Connector: CLABCONF0: = SB-iMX8PLUS
Q24 = DUAL_N-MOSFET,_0.5A_20V: CLABCONF0: = SB-iMX8PLUS
R130 R152 R270 = RESISTOR: CLABCONF0: = SB-iMX8PLUS; P/N: 161C20021S
R153 = RESISTOR: CLABCONF0: = SB-iMX8PLUS; P/N: 161C10045S
R171 = RESISTOR: CLABCONF0: = SB-iMX8PLUS; P/N: 161C12011S
R256 = RESISTOR: CLABCONF0: = SB-iMX8PLUS; P/N: 161C47025S
R264 = RESISTOR: CLABCONF0: = SB-iMX8PLUS; P/N: 161C27421S
R265 = 1K,1%,0402,1_16W: CLABCONF0: = SB-iMX8PLUS
R109 R266 = 1K,1%,0402,1_16W_2: CLABCONF0: = SB-iMX8PLUS
R126 R267 = 1K,1%,0402,1_16W_3: CLABCONF0: = SB-iMX8PLUS
R268 = 1K,1%,0402,1_16W_4: CLABCONF0: = SB-iMX8PLUS
R884 = 1K,1%,0402,1_16W_1: CLABCONF0: = SB-iMX8PLUS
U9 U13 U25 U30 U44 U66 U67 = TXS0102_0: CLABCONF0: = SB-iMX8PLUS; P/N: 116A01020S
C99 C105 C157 C907 = 100nF,_10V,_X7R,_10%,_0402_4: CLABCONF0: = SB-iMX8PLUS
C106 C153 C897 = 100nF,_10V,_X7R,_10%,_0402_11: CLABCONF0: = SB-iMX8PLUS
C94 C107 C154 C899 = 100nF,_10V,_X7R,_10%,_0402_7: CLABCONF0: = SB-iMX8PLUS
C152 C160 C900 = 100nF,_10V,_X7R,_10%,_0402_12: CLABCONF0: = SB-iMX8PLUS
C146 C164 C908 = 100nF,_10V,_X7R,_10%,_0402_10: CLABCONF0: = SB-iMX8PLUS
C101 C148 C165 C894 = 100nF,_10V,_X7R,_10%,_0402_8: CLABCONF0: = SB-iMX8PLUS
C22 C93 C167 C912 = 100nF,_10V,_X7R,_10%,_0402_5: CLABCONF0: = SB-iMX8PLUS
C95 C141 C169 C909 = 100nF,_10V,_X7R,_10%,_0402_9: CLABCONF0: = SB-iMX8PLUS
C162 C875 C876 C878 C879 C881 C901-C904 C906 = 10uF,6_0.3V,0603,20%X5R: CLABCONF0: = SB-iMX8PLUS
C100 C143 C877 C896 = 100nF,_10V,_X7R,_10%,_0402_6: CLABCONF0: = SB-iMX8PLUS
C144 C880 C898 = 100nF,_10V,_X7R,_10%,_0402_13: CLABCONF0: = SB-iMX8PLUS
E4 E9 E18 E23 = HDR_1x2_100MIL_TH_JUMPER: CLABCONF0: = SB-iMX8PLUS
OSC4 OSC5 = Osc.,_50Mhz,50PPM,_3.3V: CLABCONF0: = SB-iMX8PLUS; P/N: 141C25601S
P47 P48 = Camera_20682-030E-02: CLABCONF0: = SB-iMX8PLUS; P/N: 182K03002S
P49 P50 = FPC,_0.5mm,_22_cont_0.: CLABCONF0: = SB-iMX8PLUS; P/N: 182P02201S
R100 R225 R246 R1379 = 0R,_0402_1: CLABCONF0: = SB-iMX8PLUS
R101 = 0R,_0402_1_3: CLABCONF0: DNP
R102 R1388 = 10K,1%,0402,1_16W_8: CLABCONF0: = SB-iMX8PLUS
R104 R1386 = 2.2K,5%,0402.1_16W: CLABCONF0: = SB-iMX8PLUS
R105 R1387 = 2.2K,5%,0402.1_16W_1: CLABCONF0: = SB-iMX8PLUS
R297 R1392 = 33R,5%,0402,1_16W: CLABCONF0: DNP
R299 = 0R,_0402_1_4: CLABCONF0: = SB-iMX8PLUS
R301 R1378 = 0R,_0402_1_2: CLABCONF0: = SB-iMX8PLUS
R302 = 0R,_0402_0_2: CLABCONF0: DNP; P/N: 161C00005S
R165 R242 R303 = 0R,_0402_0: CLABCONF0: = SB-iMX8PLUS; P/N: 161C00005S
R313 R1389 = 10K,1%,0402,1_16W_9: CLABCONF0: = SB-iMX8PLUS
R314 = 10K,1%,0402,1_16W_10: CLABCONF0: = SB-iMX8PLUS
R113 R315 R1381 = 10K,1%,0402,1_16W_2: CLABCONF0: = SB-iMX8PLUS
R124 R316 R1380 = 10K,1%,0402,1_16W_5: CLABCONF0: = SB-iMX8PLUS
R193 R317 R1376 = 0R,_0402_0_1: CLABCONF0: DNP; P/N: 161C00005S
R119 R329 R1384 = 10K,1%,0402,1_16W_7: CLABCONF0: = SB-iMX8PLUS
R339 R1390 = 0R,_0402_1_1: CLABCONF0: DNP
U57 U68 = 7SZ32_OR_sgl_SC70: CLABCONF0: = SB-iMX8PLUS
U63 U65 = MAX14998ETOT: CLABCONF0: = SB-iMX8PLUS
R88 R349 = 0R: CLABCONF0: = SB-iMX8PLUS
R90 R276 = 0R_1: CLABCONF0: = SB-iMX8PLUS
R191 = 4_0.75K,1%,0402,1_16W: CLABCONF0: = SB-iMX8PLUS
R194 = 4_0.75K,1%,0402,1_16W_1: CLABCONF0: = SB-iMX8PLUS
R227 R1377 = 0R,_0402_1_4: CLABCONF0: DNP
R141 R1391 = 0R,_0402_1_3: CLABCONF0: = SB-iMX8PLUS
R89 R136 R149 R1393 = 10K,1%,0402,1_16W: CLABCONF0: = SB-iMX8PLUS
R1394 = 0R,_0402_0: CLABCONF0: DNP; P/N: 161C00005S
R224 R1395 = 10K,1%,0402,1_16W_10: CLABCONF0: DNP
R1396 = 0R,_0402_0_2: CLABCONF0: = SB-iMX8PLUS; P/N: 161C00005S
P9 = mini_PCIe_0: CLABCONF0: = SB-iMX8PLUS; P/N: 182K05202S
P20 = uSIM_SOCKET_0: CLABCONF0: = SB-iMX8PLUS
R87 = 0R_2: CLABCONF0: DNP
R135 = 1M_,5%,_0402_1: CLABCONF0: = SB-iMX8PLUS; P/N: 161C10021S
R213 = 1M_,5%,_0402: CLABCONF0: DNP; P/N: 161C10021S
R275 = 0R_3: CLABCONF0: DNP
R348 = 0R_4: CLABCONF0: = SB-iMX8PLUS
R350 = 1M_,5%,_0402_2: CLABCONF0: = SB-iMX8PLUS; P/N: 161C10021S
BH1 = BATT_HOLDER_0: CLABCONF0: = SB-iMX8PLUS
BT1 = BATT_2032: CLABCONF0: = SB-iMX8PLUS
C108 = Cap.,_47uF,_16V,_X5R: CLABCONF0: = SB-iMX8PLUS
C109 = 1uF,_16V,_X7R,_20%,_0805: CLABCONF0: = SB-iMX8PLUS
C110 = 10nF,_25V,_X7R,_10%,_0402_2: CLABCONF0: = SB-iMX8PLUS
C111 = 2.2nF,_50V,_X7R,_10%,_0402: CLABCONF0: = SB-iMX8PLUS
C112 = 47uF,6.3V,X5R_1: CLABCONF0: = SB-iMX8PLUS
C113 = Cap.,22uF,25V,_0805_1: CLABCONF0: = SB-iMX8PLUS
C114 = 100nF_0402_25V_7: CLABCONF0: = SB-iMX8PLUS
C115 = 100nF_0402_25V_2: CLABCONF0: = SB-iMX8PLUS
C116 = 2.2nF,_50V,_X7R,_10%,_0402_2: CLABCONF0: DNP
C117 = 100nF_0402_25V: CLABCONF0: = SB-iMX8PLUS
C118 = 22uF,25V,_0805: CLABCONF0: = SB-iMX8PLUS
C119 = 22uF,25V,_0805_1: CLABCONF0: = SB-iMX8PLUS
C120 = 100nF_0402_25V_4: CLABCONF0: = SB-iMX8PLUS
C121 C122 C172 C197 = 100uF,_6.3V,_X5R,_20%,_1206: CLABCONF0: = SB-iMX8PLUS
C123 = 10pF,50V,NPO,_5%,_0402: CLABCONF0: = SB-iMX8PLUS
C125 = 1uF,16V,0402: CLABCONF0: = SB-iMX8PLUS
C126 = 10nF,_25V,_X7R,_10%,_0402_3: CLABCONF0: = SB-iMX8PLUS
C128 = 2.2nF,_50V,_X7R,_10%,_0402_1: CLABCONF0: = SB-iMX8PLUS
C129 = 47uF,6.3V,X5R_2: CLABCONF0: = SB-iMX8PLUS
C130 = Cap.,22uF,25V,_0805_2: CLABCONF0: = SB-iMX8PLUS
C131 = 100nF_0402_25V_6: CLABCONF0: = SB-iMX8PLUS
C132 = 100nF_0402_25V_3: CLABCONF0: = SB-iMX8PLUS
C133 = 2.2nF,_50V,_X7R,_10%,_0402_5: CLABCONF0: = SB-iMX8PLUS
C134 = 2.2nF,_50V,_X7R,_10%,_0402_3: CLABCONF0: DNP
C135 = 100nF_0402_25V_5: CLABCONF0: = SB-iMX8PLUS
C136 = 47uF,6.3V,X5R: CLABCONF0: = SB-iMX8PLUS
C137 = Cap.,22uF,25V,_0805: CLABCONF0: = SB-iMX8PLUS
C138 = 100nF_0402_25V_1: CLABCONF0: = SB-iMX8PLUS
C139 = 10nF,_25V,_X7R,_10%,_0402_1: CLABCONF0: = SB-iMX8PLUS
C150 = 2.2nF,_50V,_X7R,_10%,_0402_4: CLABCONF0: = SB-iMX8PLUS
D3 D6 D9 = Diode_Shotky,5A,30V: CLABCONF0: = SB-iMX8PLUS
D5 = Diode_,TVS_,15V,1500W_0: CLABCONF0: = SB-iMX8PLUS; P/N: 132D00150S
DS1 DS2 = LED-GREEN_1206_2: CLABCONF0: = SB-iMX8PLUS
E6 = HDR_1x2_100MIL_TH_JUMPER_3: CLABCONF0: = SB-iMX8PLUS
E7 = HDR_1x2_100MIL_TH_JUMPER_2: CLABCONF0: = SB-iMX8PLUS
E8 E11 = HDR_1x2_100MIL_TH_JUMPER_1: CLABCONF0: = SB-iMX8PLUS
J2 = DC_Jack_,5.5_2_0.5,10A,20V: CLABCONF0: = SB-iMX8PLUS
L3 = Ind,_2.2uH,_3A_5A,_58_mOhm: CLABCONF0: = SB-iMX8PLUS; P/N: 147A2R206S
L4 L6 = IND_6.8uH_3.5A: CLABCONF0: = SB-iMX8PLUS; P/N: 147A6R801S
L5 = IND_DELTA_MPL73-2R2_2.2uH_14A: CLABCONF0: = SB-iMX8PLUS
Q2 = P-MOSFET,3A,20V,110mOhm@-1.8V: CLABCONF0: DNP
Q3 = Si7413DN: CLABCONF0: = SB-iMX8PLUS
Q13 = DUAL_N-MOSFET,_0.5A_20V: CLABCONF0: DNP
R107 = 100K,_0402_1: CLABCONF0: = SB-iMX8PLUS; P/N: 161C91011S
R108 = 100K,_1%,_0402,_1_16W_1: CLABCONF0: = SB-iMX8PLUS
R110 = 40.2k_,1%: CLABCONF0: = SB-iMX8PLUS
R111 = 10K,1%,0402,1_16W_11: CLABCONF0: = SB-iMX8PLUS; P/N: 161C20011S
R112 R148 = 47K,_0402: CLABCONF0: = SB-iMX8PLUS; P/N: 161C68001S
R114 = 100K,_1%,_0402,_1_16W_2: CLABCONF0: = SB-iMX8PLUS
R115 = 100K,_1%,_0402,_1_16W: CLABCONF0: = SB-iMX8PLUS
R116 = 100K,_0402: CLABCONF0: = SB-iMX8PLUS; P/N: 161C21531S
R117 = 100K,_0402_2: CLABCONF0: = SB-iMX8PLUS; P/N: 161C49921S
R118 = 240R_resistor,_%0.5: CLABCONF0: DNP; P/N: 161C24003S
R120 = 32.4K,_0402: CLABCONF0: = SB-iMX8PLUS; P/N: 161C32421S
R121 = 1K,1%,0402,1_16W: CLABCONF0: DNP
R122 = 0R: CLABCONF0: = SB-iMX8PLUS; P/N: 161C15021S
R123 = 40.2k_,1%_1: CLABCONF0: = SB-iMX8PLUS
R125 = 4.99K,1%,0402,1_16W: CLABCONF0: = SB-iMX8PLUS; P/N: 161C12421S
R127 = 10K,1%,0402,1_16W_12: CLABCONF0: = SB-iMX8PLUS
R131 = 10K,1%,0402,1_16W_1: CLABCONF0: DNP
R132 = 10K,1%,0402,1_16W_9: CLABCONF0: DNP
R133 = 1K,1%,0402,1_16W_4: CLABCONF0: DNP
R134 = 1K,1%,0402,1_16W_1: CLABCONF0: DNP
R144 = 953R,1%,0402,1_16W_0: CLABCONF0: = SB-iMX8PLUS; P/N: 161C91011S
R209 = CAP_NP: CLABCONF0: = SB-iMX8PLUS; P/N: 151B47500S
R238 = 10K,1%,0402,1_16W_6: CLABCONF0: DNP
R249 = 10K,1%,0402,1_16W_13: CLABCONF0: DNP
R250 = 10K,1%,0402,1_16W_3: CLABCONF0: DNP
R251 = 10K,1%,0402,1_16W_8: CLABCONF0: DNP
S2 = MISC_SHORT_NL: CLABCONF0: DNP
U18 U20 U21 = RT8272,Converter,3A,24V: CLABCONF0: = SB-iMX8PLUS
U19 = RT6239A_B: CLABCONF0: = SB-iMX8PLUS; P/N: 123V08000S
U23 = RT9186A,LDO_,2.5-5_0.5V,500mA: CLABCONF0: = SB-iMX8PLUS
C155 = 100nF,_10V,_X7R,_10%,_0402_14: CLABCONF0: = SB-iMX8PLUS
C156 = 100nF,_10V,_X7R,_10%,_0402_15: CLABCONF0: = SB-iMX8PLUS
P13 = Conn_1.,_Micro-USB,_B-Type: CLABCONF0: = SB-iMX8PLUS; P/N: 180K00501S
P16 P18 P19 = RJ11: CLABCONF0: = SB-iMX8PLUS
P23 = microSD_push-pull: CLABCONF0: = SB-iMX8PLUS; P/N: 182K01300S
Q6 = MOSFET_N_DUAL_0_0.4A_20V: CLABCONF0: = SB-iMX8PLUS
R137 = 0R,_0402_1_9: CLABCONF0: = SB-iMX8PLUS
R140 = 0R,_0402_1_8: CLABCONF0: = SB-iMX8PLUS
R142 = 0R,_0402_1_6: CLABCONF0: = SB-iMX8PLUS
R143 = 0R,_0402_1_5: CLABCONF0: = SB-iMX8PLUS
R145 = 0R,_0402_1_7: CLABCONF0: = SB-iMX8PLUS
R150 = 0R,_0402_1_1: CLABCONF0: = SB-iMX8PLUS
R226 = 0R,_0402_1_2: CLABCONF0: DNP
R245 = 0R,_0402: CLABCONF0: = SB-iMX8PLUS
R247 = 0R,_0402_2: CLABCONF0: = SB-iMX8PLUS
R248 = 0R,_0402_3: CLABCONF0: = SB-iMX8PLUS
RN6 = RN,8.2K,10P8R@1206: CLABCONF0: DNP
RN7 RN8 = RN,10K,8P4R@0805: CLABCONF0: = SB-iMX8PLUS
U11 = 74LCX04_sgl_gate_TSSOP-14: CLABCONF0: = SB-iMX8PLUS
U24 = CP2104_1: CLABCONF0: = SB-iMX8PLUS; P/N: 116A00140S
U29 = MAX3243E_RS-232_3T5R_BGA: CLABCONF0: = SB-iMX8PLUS
U31 = 24C02,_serial_EE,_2KB,_I2C: CLABCONF0: = SB-iMX8PLUS; P/N: 111S31000S

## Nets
1V5_PER : C162.1 R144.2 R242.1 U23.7(Vout1) U23.8(Vout2)
1V5_PER _EN: R146.1 U23.4(EN)
1V8_PER: C136.1 C874.1 C875.1 C906.1 C907.1 L3.2 P47.3(VCC_1P8) P48.3(VCC_1P8) R101.2 R127.1 R303.1 R1390.2 R1396.1 ; also on sheet 6 15
1V8_PER_BOOT: C139.1 U21.1(BOOT)
1V8_PER_CMP: C134.1 C150.1 U21.6(COMP)
1V8_PER_EN: R126.2 R134.2 R250.2 R251.2 U21.7(EN)
1V8_PER_FB: R124.1 R127.2 U21.5(FB)
1V8_PER_RC: C150.2 R122.2
1V8_PER_SS: C135.1 U21.8(SS)
1V8_PER_SW: C139.2 D9.CATHODE L3.1 U21.3(SW)
3V3_AW_BOOT: C126.1 U20.1(BOOT)
3V3_AW_CMP: C128.1 C133.1 U20.6(COMP)
3V3_AW_EN: R121.2 R130.2 R209.2 R224.2 U20.7(EN)
3V3_AW_FB: R120.1 R125.1 U20.5(FB)
3V3_AW_RC: C128.2 R123.1
3V3_AW_SS: C132.1 U20.8(SS)
3V3_AW_SW: C126.2 D6.CATHODE L6.1 U20.3(SW)
3V3_DBGUART232_RXD: U29.18(R1OUT) U30.1(B2)
3V3_DBGUART232_TXD: U29.12(T1IN) U30.8(B1)
3V3_DBGUARTUSB_RXD: U24.20(RXD) U25.1(B2)
3V3_DBGUARTUSB_TXD: U24.21(TXD) U25.8(B1)
3V3_PER: C1.1 C22.1 C27.1 C65.2 C92.1 C93.1 C94.1 C95.1 C96.1 C97.1 C98.1 C105.2 C129.1 C143.1 C145.1 C146.1 C147.1 C148.1 C149.1 C152.1 C153.1 C155.2 C158.2 C159.2 C160.2 C161.1 C164.1 C169.1 C170.2 C191.1 C200.1 C202.1 C876.1 C877.1 C878.1 C879.1 C880.1 C881.1 C894.2 C895.2 C896.2 C897.2 C898.1 C900.1 C901.1 C902.1 C903.1 C904.1 C905.1 C908.1 D24.2(ANODE) E11.1 E18.1 E23.1 L6.2 P5.3 P9.2(+3.3V_1) P9.24(+3.3V_AUX) P9.39(RSVD6) P9.41(RSVD7) P9.52(+3.3V_2) P11.38 P11.39 P23.P4(VDD) P47.1(VCC1_3P3) P47.2(VCC2_3P3) P48.1(VCC1_3P3) P48.2(VCC2_3P3) P49.22 P50.22 Q24.2(G1) Q24.5(G2) R3.2 R9.1 R54.1 R56.1 R60.1 R62.1 R100.1 R120.2 R135.2 R146.2 R148.1 R152.2 R153.2 R165.1 R191.1 R194.1 R213.2 R225.2 R226.2 R227.2 R265.1 R266.1 R270.1 R302.1 R350.2 R1391.1 R1394.1 RN6.5(COM1) RN6.10(COM2) RN8.1(RA1) RN8.2(RB1) U9.3(VCCA) U13.7(VCCB) U23.1(Vin1) U23.2(Vin2) U25.3(VCCA) U27.5(VBUS) U28.5(VBUS) U29.21(FORCEOFF) U29.22(FORCEON) U29.26(VCC3) U30.3(VCCA) U30.7(VCCB) U31.8(VCC) U33.5(VBUS) U44.7(VCCB) U63.1(VDD) U63.6(VDD_1) U63.13(VDD_2) U63.26(VDD_3) U65.1(VDD) U65.6(VDD_1) U65.13(VDD_2) U65.26(VDD_3) U66.7(VCCB) U67.7(VCCB) ; also on sheet 2 4 5 6 7 15
3V3_RTC: D8.ANODE R165.2
5V0_PER: C112.1 F4.2 L4.2 R73.1 R107.1 ; also on sheet 4 6
5V0_PER_BOOT: C110.1 U18.1(BOOT)
5V0_PER_CMP: C111.1 C116.1 U18.6(COMP)
5V0_PER_EN: R109.2 R133.2 R238.2 R249.2 U18.7(EN)
5V0_PER_FB: R107.2 R111.1 U18.5(FB)
5V0_PER_RC: C111.2 R110.1
5V0_PER_SS: C115.1 U18.8(SS)
5V0_PER_SW: C110.2 D3.CATHODE L4.1 U18.3(SW)
GND: BH1.1(MINUS) C1.2 C22.2 C27.2 C55.2 C56.2 C57.2 C58.2 C64.1 C65.1 C67.1 C82.1 C92.2 C93.2 C94.2 C95.2 C96.2 C97.2 C98.2 C99.2 C100.2 C101.2 C104.2 C105.1 C106.2 C107.2 C108.2 C109.2 C112.2 C113.2 C114.2 C115.2 C116.2 C117.2 C118.2 C119.2 C121.1 C122.1 C129.2 C130.2 C131.2 C132.2 C133.2 C134.2 C135.2 C136.2 C137.2 C138.2 C140.2 C141.2 C142.2 C143.2 C144.2 C145.2 C146.2 C147.2 C148.2 C149.2 C152.2 C153.2 C154.2 C155.1 C157.2 C158.1 C159.1 C160.1 C161.2 C162.2 C164.2 C165.2 C167.2 C168.2 C169.2 C170.1 C172.1 C191.2 C197.1 C198.2 C200.2 C201.1 C202.2 C359.2 C874.2 C875.2 C876.2 C877.2 C878.2 C879.2 C880.2 C881.2 C894.1 C895.1 C896.1 C897.1 C898.2 C899.2 C900.2 C901.2 C902.2 C903.2 C904.2 C905.2 C906.2 C907.2 C908.2 C909.2 C910.2 C911.2 C912.2 D3.ANODE D5.2 D6.ANODE D9.ANODE DS1.CATHODE E4.2 E9.1 J2.2(R) J2.3(Plastic) J2.SH1 J2.SH2 J2.SH3 J2.SH4 L1.5(GND) L1.6(GND) L2.5(GND) L2.6(GND) L7.5(GND) L7.6(GND) L10.5(GND) L10.6(GND) L12.5(GND) L12.6(GND) L13.5(GND) L13.6(GND) L25.5(GND) L25.6(GND) L27.5(GND) L27.6(GND) L28.5(GND) L28.6(GND) L29.5(GND) L29.6(GND) L30.5(GND) L30.6(GND) OSC4.2(GND) OSC5.2(GND) P5.1 P5.8 P5.9 P5.10 P9.4(GND7) P9.9(GND1) P9.15(GND2) P9.18(GND8) P9.21(GND3) P9.26(GND9) P9.27(GND4) P9.29(GND5) P9.34(GND10) P9.35(GND6) P9.37(RSVD5) P9.40(GND11) P9.50(GND12) P11.11 P11.16 P11.19 P11.22 P11.25 P11.28 P11.31 P11.34 P13.5(GND) P13.6(SHIELD1) P13.7(SHIELD2) P13.8(SHIELD3) P13.9(SHIELD4) P14.2(D2_Shield) P14.5(D1_Shield) P14.8(D0_Shield) P14.11(CK_Shield) P14.17(GND) P14.20(SHELL1) P14.21(SHELL2) P16.2 P16.5 P18.2 P18.5 P19.2 P19.5 P20.5(GND) P20.9(M9) P20.10(M10) P20.11(M11) P20.12(M12) P23.G1 P23.G2 P23.G3 P23.G4 P23.P6(VSS) P23.SH1 P23.SH2 P47.4(GND1) P47.5(GND2) P47.9(GND3) P47.14(GND4) P47.17(GND5) P47.18(GND6) P47.22(GND7) P47.26(GND8) P47.SH1 P47.SH2 P47.SH3 P47.SH4 P47.SH5 P47.SH6 P47.SH7 P47.SH8 P47.SH9 P47.SH10 P47.SH11 P47.SH12 P47.SH13 P47.SH14 P47.SH15 P47.SH16 P47.SH17 P47.SH18 P47.SH19 P48.4(GND1) P48.5(GND2) P48.9(GND3) P48.14(GND4) P48.17(GND5) P48.18(GND6) P48.22(GND7) P48.26(GND8) P48.SH1 P48.SH2 P48.SH3 P48.SH4 P48.SH5 P48.SH6 P48.SH7 P48.SH8 P48.SH9 P48.SH10 P48.SH11 P48.SH12 P48.SH13 P48.SH14 P48.SH15 P48.SH16 P48.SH17 P48.SH18 P48.SH19 P49.1 P49.4 P49.7 P49.10 P49.13 P49.16 P49.19 P49.NC1 P49.NC2 P50.1 P50.4 P50.7 P50.10 P50.13 P50.16 P50.19 P50.NC1 P50.NC2 Q2.3(D) Q6.1(S1) Q6.4(S2) Q13.1(S1) Q13.4(S2) Q14.4(S) R55.2 R59.2 R61.2 R63.2 R64.2 R89.2 R103.1 R108.2 R110.2 R111.2 R115.1 R122.1 R123.2 R124.2 R125.2 R136.2 R149.1 R209.1 R249.1 R251.1 R256.1 R313.1 R314.1 R316.1 R328.1 R341.1 R884.2 R1375.1 R1381.1 R1384.1 R1385.1 R1389.1 R1395.1 RN7.1(RA1) RN7.2(RB1) RN7.3(RC1) RN7.4(RD1) RN8.3(RC1) S2.2 U5.4(GND) U9.2(GND) U13.2(GND) U18.4(GND) U18.9(PAD) U19.9(GND) U19.10(GND) U19.11(GND) U19.12(GND) U20.4(GND) U20.9(PAD) U21.4(GND) U21.9(PAD) U23.5(GND) U23.9(EPAD) U24.2(GND) U24.25(CPAD) U25.2(GND) U26.2(GND) U27.2(GND) U28.2(GND) U29.4(R4IN) U29.5(R5IN) U29.24(GND) U29.33(EPAD) U30.2(GND) U31.4(GND) U33.2(GND) U38.2(GND) U44.2(GND) U57.3(GND) U63.Tpad U65.Tpad U66.2(GND) U67.2(GND) U68.3(GND) ; also on sheet 2 3 4 5 6 7 15
VCC_RTC: C198.1 E6.2 ; also on sheet 2
VDD_3P3_CN: D24.1(CATHODE) R264.2
CARRIER_EEPROM_WP: E11.2 R149.2 U31.7(WP)
CSI1_B_FLASH_OUT: U13.1(B2) ; also on sheet 6
CSI1_B_FLASH_OUT_1V8: P48.29(FLASH) R301.1
CSI1_B_RST: R340.2 ; also on sheet 6
CSI1_B_RST_1V8: P48.21(RESET) R340.1 R341.2
CSI1_B_TRG: R317.1 U13.8(B1) ; also on sheet 6
CSI1_B_TRG_1V8: P48.12(TRIGGER) R299.1
CSI1_CKN: U63.5(COM1-) ; also on sheet 2
CSI1_CKP: U63.4(COM1+) ; also on sheet 2
CSI1_DN0: U63.8(COM2-) ; also on sheet 2
CSI1_DN1: U63.10(COM3-) ; also on sheet 2
CSI1_DN2: U63.12(COM4-) ; also on sheet 2
CSI1_DN3: U63.3(COM0-) ; also on sheet 2
CSI1_DP0: U63.7(COM2+) ; also on sheet 2
CSI1_DP1: U63.9(COM3+) ; also on sheet 2
CSI1_DP2: U63.11(COM4+) ; also on sheet 2
CSI1_DP3: U63.2(COM0+) ; also on sheet 2
CSI1_GPIO_1V8_ENABLE: R313.2 R327.1 U13.6(OE)
CSI1_I2C_1V8_ENABLE: R314.2 R329.1 U44.6(OE)
CSI1_MCLK_B: P48.13(RSVD1) R297.2
CSI1_MCLK_VCC_B: C165.1 OSC4.4(VCC) R100.2 R101.1 R102.1
CSI1_P22_CKN: P49.8 U63.39(NC1-)
CSI1_P22_CKP: P49.9 U63.40(NC1+)
CSI1_P22_DN0: P49.2 U63.37(NC2-)
CSI1_P22_DN1: P49.5 U63.35(NC3-)
CSI1_P22_DN2: P49.11 U63.24(NC4-)
CSI1_P22_DN3: P49.14 U63.41(NC0-)
CSI1_P22_DP0: P49.3 U63.38(NC2+)
CSI1_P22_DP1: P49.6 U63.36(NC3+)
CSI1_P22_DP2: P49.12 U63.25(NC4+)
CSI1_P22_DP3: P49.15 U63.42(NC0+)
CSI1_P30_CKN: P48.24(MIPI_CLK_N) U63.31(NO1-)
CSI1_P30_CKP: P48.25(MIPI_CLK_P) U63.32(NO1+)
CSI1_P30_DN0: P48.19(MIPI_D0_N) U63.29(NO2-)
CSI1_P30_DN1: P48.15(MIPI_D1_N) U63.27(NO3-)
CSI1_P30_DN2: P48.10(MIPI_D2_N) U63.20(NO4-)
CSI1_P30_DN3: P48.27(MIPI_D3_N) U63.33(NO0-)
CSI1_P30_DP0: P48.20(MIPI_D0_P) U63.30(NO2+)
CSI1_P30_DP1: P48.16(MIPI_D1_P) U63.28(NO3+)
CSI1_P30_DP2: P48.11(MIPI_D2_P) U63.21(NO4+)
CSI1_P30_DP3: P48.28(MIPI_D3_P) U63.34(NO0+)
CSI1_PWR_DWN_B: R315.2 ; also on sheet 6
CSI1_PWR_DWN_B_1V8: P48.6(PWDN) R315.1 R316.2
CSI1_SELECTOR: E18.2 R327.2 R328.2 R329.2 U63.16(SEL1) U63.17(SEL2)
CSI2_B_FLASH_OUT: U66.1(B2) ; also on sheet 6
CSI2_B_FLASH_OUT_1V8: P47.29(FLASH) R1379.1
CSI2_B_RST: R1383.2 ; also on sheet 6
CSI2_B_RST_1V8: P47.21(RESET) R1383.1 R1385.2
CSI2_B_TRG: R1376.1 U66.8(B1) ; also on sheet 6
CSI2_B_TRG_1V8: P47.12(TRIGGER) R1378.1
CSI2_CKN: U65.5(COM1-) ; also on sheet 2
CSI2_CKP: U65.4(COM1+) ; also on sheet 2
CSI2_DN0: U65.8(COM2-) ; also on sheet 2
CSI2_DN1: U65.10(COM3-) ; also on sheet 2
CSI2_DN2: U65.12(COM4-) ; also on sheet 2
CSI2_DN3: U65.3(COM0-) ; also on sheet 2
CSI2_DP0: U65.7(COM2+) ; also on sheet 2
CSI2_DP1: U65.9(COM3+) ; also on sheet 2
CSI2_DP2: U65.11(COM4+) ; also on sheet 2
CSI2_DP3: U65.2(COM0+) ; also on sheet 2
CSI2_GPIO_1V8_ENABLE: R1380.1 R1381.2 U66.6(OE)
CSI2_I2C_1V8_ENABLE: R1388.1 R1389.2 U67.6(OE)
CSI2_MCLK_B: P47.13(RSVD1) R1392.2
CSI2_MCLK_VCC_B: C911.1 OSC5.4(VCC) R1390.1 R1391.2 R1393.1
CSI2_P22_CKN: P50.8 U65.39(NC1-)
CSI2_P22_CKP: P50.9 U65.40(NC1+)
CSI2_P22_DN0: P50.2 U65.37(NC2-)
CSI2_P22_DN1: P50.5 U65.35(NC3-)
CSI2_P22_DN2: P50.11 U65.24(NC4-)
CSI2_P22_DN3: P50.14 U65.41(NC0-)
CSI2_P22_DP0: P50.3 U65.38(NC2+)
CSI2_P22_DP1: P50.6 U65.36(NC3+)
CSI2_P22_DP2: P50.12 U65.25(NC4+)
CSI2_P22_DP3: P50.15 U65.42(NC0+)
CSI2_P30_CKN: P47.24(MIPI_CLK_N) U65.31(NO1-)
CSI2_P30_CKP: P47.25(MIPI_CLK_P) U65.32(NO1+)
CSI2_P30_DN0: P47.19(MIPI_D0_N) U65.29(NO2-)
CSI2_P30_DN1: P47.15(MIPI_D1_N) U65.27(NO3-)
CSI2_P30_DN2: P47.10(MIPI_D2_N) U65.20(NO4-)
CSI2_P30_DN3: P47.27(MIPI_D3_N) U65.33(NO0-)
CSI2_P30_DP0: P47.20(MIPI_D0_P) U65.30(NO2+)
CSI2_P30_DP1: P47.16(MIPI_D1_P) U65.28(NO3+)
CSI2_P30_DP2: P47.11(MIPI_D2_P) U65.21(NO4+)
CSI2_P30_DP3: P47.28(MIPI_D3_P) U65.34(NO0+)
CSI2_PWR_DWN_B: R1382.2 ; also on sheet 6
CSI2_PWR_DWN_B_1V8: P47.6(PWDN) R1382.1 R1384.2
CSI2_SELECTOR: E23.2 R1375.2 R1380.2 R1388.2 U65.16(SEL1) U65.17(SEL2)
EARC_N: C358.2 L29.3 R171.2
EARC_N_HPD: C358.1 ; also on sheet 2
EARC_P: C360.2 L29.4
EARC_P_UTIL: C360.1 ; also on sheet 2
EPR_A0: R226.1 RN7.8(RA2) U31.1(A0)
EPR_A1: R227.1 RN7.7(RB2) U31.2(A1)
EPR_A2: R225.1 RN7.6(RC2) U31.3(A2)
FB_LDO_1V5: R136.1 R144.1 U23.6(ADJ)
FPC22_17: P49.17 R317.2
FPC22_17B: P50.17 R1376.2
FPC22_18: P49.18 R339.1
FPC22_18B: P50.18 R1377.1
HDMI_5V_FL: C359.1 D23.2(ANODE) F4.1
HDMI_5VSCHT: C67.2 C82.2 D23.1(CATHODE) P14.18(+5V) R267.1 R268.1 R884.1 U9.7(VCCB) U38.1(IO1) U38.5(VBUS)
HDMI_CEC: D25.2(ANODE) Q24.4(S2) R152.1 ; also on sheet 2
HDMI_CEC_3P3: D25.1(CATHODE) P14.13(CE_Remote) Q24.3(D2) R264.1 U38.6(IO4)
HDMI_DDC_SCL: R266.2 U9.5(A1) ; also on sheet 2
HDMI_DDC_SDA: R265.2 U9.4(A2) ; also on sheet 2
HDMI_HPD: Q24.1(S1) R153.1 ; also on sheet 2
HDMI_HPD_5V: Q24.6(D1) R171.1 R256.2
HDMI_HPD_CN: L29.2 P14.19(HP_DET)
HDMI_TXCN: L30.3 ; also on sheet 2
HDMI_TXCP: L30.4 ; also on sheet 2
HDMI_TXN0: L28.3 ; also on sheet 2
HDMI_TXN1: L25.3 ; also on sheet 2
HDMI_TXN2: L27.3 ; also on sheet 2
HDMI_TXP0: L28.4 ; also on sheet 2
HDMI_TXP1: L25.4 ; also on sheet 2
HDMI_TXP2: L27.4 ; also on sheet 2
HDMI_UTILITY_CN: L29.1 P14.14(NC)
I2C3_SCL_1V8: P48.7(I2C_SCL) R105.1 U44.4(A2)
I2C3_SCL_CM: P5.4 P9.30(SMB_CLK) P49.20 U31.6(SCL) U33.1(IO1) U44.1(B2) ; also on sheet 4 5 6 7
I2C3_SDA_1V8: P48.8(I2C_SDA) R104.1 U44.5(A1)
I2C3_SDA_CM: P5.5 P9.32(SMB_DATA) P49.21 U31.5(SDA) U33.3(IO2) U44.8(B1) ; also on sheet 4 5 6 7
I2C4_SCL: R88.2 R194.2 R275.2 ; also on sheet 2 6
I2C4_SCL_1V8: P47.7(I2C_SCL) R1387.1 U67.4(A2)
I2C4_SCL_CM: P50.20 R88.1 U67.1(B2)
I2C4_SDA: R90.2 R191.2 ; also on sheet 2 6
I2C4_SDA_1V8: P47.8(I2C_SDA) R1386.1 U67.5(A1)
I2C4_SDA_CM: P50.21 R90.1 U67.8(B1)
LED_USBSERIALEN: R150.2 U11.13(I)
LVDS0_CLK_N: L13.3 ; also on sheet 2
LVDS0_CLK_P: L13.4 ; also on sheet 2
LVDS0_CLKN: L13.2 P11.24
LVDS0_CLKP: L13.1 P11.23
LVDS0_N0: L2.1 P11.33
LVDS0_N1: L1.1 P11.30
LVDS0_N2: L7.1 P11.27
LVDS0_N3: L12.1 P11.21
LVDS0_P0: L2.2 P11.32
LVDS0_P1: L1.2 P11.29
LVDS0_P2: L7.2 P11.26
LVDS0_P3: L12.2 P11.20
LVDS0_TX0_N: L2.4 ; also on sheet 2
LVDS0_TX0_P: L2.3 ; also on sheet 2
LVDS0_TX1_N: L1.4 ; also on sheet 2
LVDS0_TX1_P: L1.3 ; also on sheet 2
LVDS0_TX2_N: L7.4 ; also on sheet 2
LVDS0_TX2_P: L7.3 ; also on sheet 2
LVDS0_TX3_N: L12.4 ; also on sheet 2
LVDS0_TX3_P: L12.3 ; also on sheet 2
LVDS_COMP: C58.1 U5.5(COMP)
LVDS_DIMO: P11.14 TP4.1
LVDS_DISP_RESET: C64.2 P11.36 R3.1 ; also on sheet 6
LVDS_L_R: P11.8 R56.2 R59.1
LVDS_LED_EN: R52.2 U5.2(CTRL) ; also on sheet 5
LVDS_LED_N: R65.1 R66.1 R68.2 U5.6(FB)
LVDS_LED_NEG: C85.1 P11.9 P11.10 R68.1
LVDS_LED_P: C57.1 D11.CATHODE R67.2
LVDS_LED_POS: C85.2 P11.1 P11.2 R67.1
LVDS_RESET: R63.1 R65.2 R66.2
LVDS_SELB: P11.13 R62.2 R64.1
LVDS_STBYB: P11.35 R54.2 R55.1
LVDS_SW_PWR_IN: C55.1 C56.1 L9.1 R52.1 R73.2 U5.1(IN)
LVDS_TOUCH_RESET: P5.7 U33.6(IO4) ; also on sheet 6
LVDS_U_D: P11.7 R60.2 R61.1
LVDS_WLD_SW: D11.ANODE L9.2 U5.3(SW)
mPCIe_PERST: P9.22(PERST#) R89.1 R193.2 R213.1 ; also on sheet 6
mPCIE_USB_DN: L10.4 P9.36(USB_D-)
mPCIE_USB_DP: L10.3 P9.38(USB_D+)
mux_PCIe_USB_DN: L10.1 ; also on sheet 4
mux_PCIe_USB_DP: L10.2 ; also on sheet 4
nUSBSERIALEN: Q6.5(G2) Q6.6(D1) RN8.8(RA2) U30.6(OE)
OE_DDC_LS: R270.2 U9.6(OE)
OSC4_EN: OSC4.1(EN) R102.2 R103.2
OSC4_OUT: OSC4.3(OUT) U57.1(A) U57.2(B)
OSC5_EN: OSC5.1(EN) R1393.2 R1395.2
OSC5_OUT: OSC5.3(OUT) U68.1(A) U68.2(B)
P_AGND: C124.2 C125.2 R117.2 S2.1 U19.1(AGND)
PCI_1V5: C99.1 C100.1 C101.1 C104.1 P9.6(+1.5V_1) P9.28(+1.5V_2) P9.48(+1.5V_3) R242.2
PCIE_CLKN: R348.1 ; also on sheet 2
PCIE_CLKP: R349.1 ; also on sheet 2
PCIE_CLKREQ#: P9.7(CLKREQ#) R135.1 R275.1 R276.1
PCIe_REFCLKN: P9.11(REFCLK-) R348.2
PCIe_REFCLKP: P9.13(REFCLK+) R349.2
PCIE_RXN: P9.23(PER_N0) ; also on sheet 2
PCIE_RXP: P9.25(PER_P0) ; also on sheet 2
PCIE_TXN: P9.31(PET_N0) ; also on sheet 2
PCIE_TXP: P9.33(PET_P0) ; also on sheet 2
PCIE_WAKE#: P9.1(WAKE#) R87.1 R350.1
PMIC_ON_REQ: Q13.5(G2) R130.1 R133.1 R134.1 ; also on sheet 2
PMIC_ON_REQn: Q13.2(G1) Q13.3(D2) R132.2
PMIC_STBY_REQ: Q14.5(G) ; also on sheet 2
POR_B_3P3: R193.1 ; also on sheet 2 6
PWR_CTRL: Q13.6(D1) Q14.3(D) R109.1 R121.1 R126.1 R131.2
Q66_4: R1379.2 U66.4(A2)
Q66_5: R1378.2 U66.5(A1)
Q68_4: R1392.1 U68.4(A+B)
RS232_RXD_UART1: P16.4 U29.2(R2IN)
RS232_RXD_UART4: P18.4 U29.3(R3IN)
RS232_TXD_UART1: P16.3 U29.7(T2OUT)
RS232_TXD_UART4: P18.3 U29.8(T3OUT)
RS232DB_LED: DS2.ANODE R148.2
RS232DB_LEDCAT: DS2.CATHODE U11.12
RS232DB_RXD_DBG: P19.4 U29.1(R1IN)
RS232DB_TXD_DBG: P19.3 U29.6(T1OUT)
SD1_DATA5: R276.2 ; also on sheet 2 6
SD1_DATA7: R87.2 ; also on sheet 2 6
SD2_CLK: R143.2 ; also on sheet 2
SD2_CMD: R145.2 ; also on sheet 2
SD2_DATA0: R140.2 ; also on sheet 2
SD2_DATA1: R137.2 ; also on sheet 2
SD2_DATA2: R141.2 ; also on sheet 2
SD2_DATA3: R142.2 ; also on sheet 2
SD2_nCD: P23.P9(CD#) R9.2 ; also on sheet 2
SD2_WP: P5.6 U33.4(IO3) ; also on sheet 2
SDCARD_CLK: P23.P5(CLK) R143.1 RN6.7(R6) U27.3(IO2)
SDCARD_CMD: P23.P3(CMD) R145.1 RN6.8(R7) U28.6(IO4)
SDCARD_DAT0: P23.P7(DAT0) R140.1 RN6.1(R1) U27.1(IO1)
SDCARD_DAT1: P23.P8(DAT1) R137.1 RN6.2(R2) U27.6(IO4)
SDCARD_DAT2: P23.P1(DAT2) R141.1 RN6.3(R3) U28.1(IO1)
SDCARD_DAT3: P23.P2(DAT3) R142.1 RN6.4(R4) U28.4(IO3)
SERIAL_VBUS: C142.1 P13.1(VBUS) R222.1 U24.7(REGIN) U24.8(VBUS) U26.4(IO3)
SIM1_CLK: P9.12(UIM_CLK) P20.3(CLK)
SIM1_IO: P9.10(UIM_DATA) P20.7(IO)
SIM1_RST: P9.14(UIM_RESET) P20.2(RST)
SIM1_VCC: C201.2 P9.8(UIM_PWR) P20.1(VCC)
SIM1_VPP: P9.16(UIM_VPP) P20.6(VPP)
SP_PMP_C1N: C156.2 U29.23(C1-)
SP_PMP_C1P: C156.1 U29.28(C1+)
SP_PMP_C2N: C151.2 U29.30(C2-)
SP_PMP_C2P: C151.1 U29.29(C2+)
SP_PMP_VN: C154.1 U29.31(V-)
SP_PMP_VP: C157.1 U29.27(V+)
TMDS1_CLK_LN: L30.2 P14.12(CK-)
TMDS1_CLK_LP: L30.1 P14.10(CK+)
TMDS1_DCLK: P14.15(DDC_CLK) R267.2 U9.8(B1) U38.4(IO3)
TMDS1_DDAT: P14.16(DDC_DATA) R268.2 U9.1(B2) U38.3(IO2)
TMDS1_TX0_LN: L28.2 P14.9(D0-)
TMDS1_TX0_LP: L28.1 P14.7(D0+)
TMDS1_TX1_LN: L25.2 P14.6(D1-)
TMDS1_TX1_LP: L25.1 P14.4(D1+)
TMDS1_TX2_LN: L27.2 P14.3(D2-)
TMDS1_TX2_LP: L27.1 P14.1(D2+)
U13_A1: R299.2 U13.5(A1)
U13_A2: R301.2 U13.4(A2)
U57_4: R297.1 U57.4(A+B)
UART1_R2OUT: R247.2 U29.17(R2OUT)
UART1_RXD: R247.1 ; also on sheet 2
UART1_T2IN: R245.2 U29.11(T2IN)
UART1_TXD: R245.1 ; also on sheet 2
UART2_RXD: U25.5(A1) U30.4(A2) ; also on sheet 2
UART2_TXD: U25.4(A2) U30.5(A1) ; also on sheet 2
UART4_R3OUT: R248.2 U29.15(R3OUT)
UART4_RXD: R248.1 ; also on sheet 2
UART4_T3IN: R246.2 U29.10(T3IN)
UART4_TXD: R246.1 ; also on sheet 2
UART_DEBUGSEL: E4.1 Q6.2(G1) R222.2 RN8.6(RC2) ; also on sheet 6
USBSERIAL_3V45: C140.1 C141.1 C144.1 RN8.4(RD1) U24.5(VIO) U24.6(VDD) U25.7(VCCB)
USBSERIAL_DN: P13.2(D-) U24.4(DN) U26.6(IO4)
USBSERIAL_DP: P13.3(D+) U24.3(DP) U26.1(IO1)
USBSERIAL_nRST: RN8.5(RD2) U24.9(RST#)
USBSERIALEN: Q6.3(D2) R150.1 RN8.7(RB2) U25.6(OE)
V_RTC: D4.CATHODE D8.CATHODE E6.1
V_SOM: C121.2 C122.2 E7.1 E8.1 Q3.5(D) Q3.6(D) Q3.7(D) Q3.8(D) Q3.9(D-pad) R112.1 R118.1 R131.1 R132.1 ; also on sheet 2 15
V_SOM_BOOT: C120.1 U19.5(BOOT)
V_SOM_DSCHG: Q2.2(S) R118.2
V_SOM_EN: R113.2 R115.2 U19.13(EN)
V_SOM_FB: C123.2 R116.1 R117.1 U19.2(FB)
V_SOM_L: C123.1 C172.2 C197.2 E7.2 E8.2 L5.2 Q3.1(S) Q3.2(S) Q3.3(S) R116.2 R119.1
V_SOM_LX: C120.2 L5.1 U19.6(SW)
V_SOM_PG: Q2.1(G) R114.2 U19.4(PGOOD)
V_SOM_PVCC: C125.1 U19.3(PVCC)
V_SOM_SS: C124.1 U19.14(SS)
VCOIN: BH1.2(PLUS) D4.ANODE
VDC_IN: C108.1 C109.1 C113.1 C114.1 C117.1 C118.1 C119.1 C130.1 C131.1 C137.1 C138.1 D5.1 J2.1(CENTRAL) R108.1 R113.1 R114.1 R224.1 R238.1 R250.1 U18.2(Vin) U19.7(VIN) U19.8(VIN) U20.2(Vin) U21.2(Vin)
VIO_CAMERA_CSI1: C106.1 C107.1 C167.1 C168.1 R104.2 R105.2 R302.2 R303.2 U13.3(VCCA) U44.3(VCCA) U57.5(VCC)
VIO_CAMERA_CSI2: C899.1 C909.1 C910.1 C912.1 R1386.2 R1387.2 R1394.2 R1396.2 U66.3(VCCA) U67.3(VCCA) U68.5(VCC)
VSOM_BP_EN#: E9.2 Q3.4(G) R119.2
VSOM_LED: DS1.ANODE R112.2

Not connected (* = marked no-connect by the designer): P5 2*; P9 3(RSVD1)* 5(RSVD2)* 17(RSVD3)* 19(RSVD4)* 20(RSVD18)* 42(LED_WWAN#)* 43(RSVD8)* 44(LED_WLAN#)* 45(RSVD9)* 46(LED_WPAN#)* 47(RSVD10)* 49(RSVD11)* 51(RSVD12)*; P11 3* 4* 5* 6* 12* 15* 17* 18* 37* 40*; P13 4(ID)* 10(NC1)* 11(NC2)*; P16 1* 6*; P18 1* 6*; P19 1* 6*; P20 4(RSVD4)* 8(RSVD8)*; P47 23(RSVD2)* 30(RSVD3)*; P48 23(RSVD2)* 30(RSVD3)*; R339 2*; R1377 2*; RN6 6(R5)* 9(R8)*; RN7 5(RD2)*; U23 3(PGOOD)*; U24 1(RI)* 10(NC)* 11(GPIO3)* 12(GPIO2)* 13(GPIO1)* 14(GPIO0)* 15(SUSPEND#)* 16(VPP)* 17(SUSPEND)* 18(CTS)* 19(RTS)* 22(DSR)* 23(DTR)* 24(DCD)*; U26 3(IO2)* 5(VBUS)*; U27 4(IO3)*; U28 3(IO2)*; U29 9(NC)* 13(R5OUT)* 14(R4OUT)* 16(NC)* 19(R2OUTB)* 20(INVALID)* 25(NC)* 32(NC)*; U63 14(COM5+)* 15(COM5-)* 18(NO5-)* 19(NO5+)* 22(NC5-)* 23(NC5+)*; U65 14(COM5+)* 15(COM5-)* 18(NO5-)* 19(NO5+)* 22(NC5-)* 23(NC5+)*

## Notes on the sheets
sheet 8
- LVDS connector
- LCD back-light power
- DNP
- DNP
- 9.6V/270mA
- SPDIF_RX = PWM2_OUT
- # 100-Ohm diff pairs
- # 100-Ohm diff pairs
- DNP
- DNP
- DNP
- DNP
- DNP
- LVDS Touch-panel connector
- INT
- SD2_WP = GPIO2_20
- Pinout of J5 reversed
   to FPC
sheet 9
- HDMI connector with eARC
- # 100-Ohm diff pairs
- # 100-Ohm diff pairs
- eARC ESD and HPD DC Filter
- # 100-Ohm diff pairs
- DDC Level Shifter
- HPD and CEC Level Shifter
sheet 10
- MIPI-CSI1 Connectors
- MIPI-CSI1 (22-pin, 3.3V)
- 22-pin Connector for RPi cameras
  Four MIPI-CSI lanes connected
- # 100-Ohm diff pairs
- # 100-Ohm diff pairs
- DNP
- DNP
- MIPI-CSI1 (30-pin, 1.8V)
- OE VCCA
  domain
- R327,R313 - 3.3->1.8 Divider
- R329,R314 - 3.3->1.8 Divider
- # 100-Ohm diff pairs
- 30 pin Connector for e-CAM130_iMX8M
  (e-con System)
- DNP
- DNP
- DNP
sheet 11
- MIPI-CSI2 (22-pin, 3.3V)
- MIPI-CSI2 Connectors
- 22-pin Connector for RPi cameras
  Four MIPI-CSI lanes connected
- # 100-Ohm diff pairs
- # 100-Ohm diff pairs
- DNP
- DNP
- MIPI-CSI2 (30-pin, 1.8V)
- OE VCCA
  domain
- R327,R313 - 3.3->1.8 Divider
- R329,R314 - 3.3->1.8 Divider
- # 100-Ohm diff pairs
- 30 pin Connector for e-CAM130_iMX8M
  (e-con System)
- DNP
- DNP
- DNP
sheet 12
- mini PCIe socket & SIM socket
- GPIO2 [7]
- GPIO2 [9]
- DNP
- DNP
- DNP
- uSIM socket
sheet 13
- POWER
- 3V3_PER
- DC input
- MAX 16V
- DNP
- 12V domain
- Note: R209 is Capacitor-4.7uF
- H=4.2mm
- Vout=Vfb*(1+Rt/Rb)=
  0.92*(1+32.4/12.4)=3.32V@3A
- DNP
- 12V domain
- DNP
- V_SOM
  discharge
- V_SOM
- Vout = 0.7x(1+Rup/Rdn)=0.7*(1+215/49.9)=3.72@9A
- 12V domain
- to 100 mill header
- 1V5_PER source
- DNP
- >1.6V
- Vin 4.5-18V
- 10mA OD
- Current measure
- Vout=Vfb*(1+Rt/Rb)=0.8*(1+9.1/10)=1.528V
- 12V domain
- Vgs up to 12V
- DNP
- 1V8_PER source
- RTC battery
- 5V0_PER source
- DNP
- DNP
- DNP
- DNP
- min 6.8uH
- DNP
- Install by default
- DNP
- H=4.2mm
- Vout=Vfb*(1+Rt/Rb)=
  0.92*(1+10K/10K)=1.84V@3A
- Vout=Vfb*(1+Rt/Rb)=
  0.92*(1+9.1K/2K)=5.106V@3A
- 12V domain
- up to 24V
- 12V domain
- up to 24V
- DNP
- DNP
sheet 14
- Serial debug console
- Micro-SD socket (bootable)
- DEBUG PORT
  (microUSB2.0 Type B)
  UART over USB
- DNP
- In
- Out
- O
- O
- Debug USB Serial (UART2)
- Jumper removed: Automatic Mode
      Debug over USB when USB host
  provides VBUS
      Debug over RS-232 when USB VBUS not
  available
  Jumper assembled: Force RS232
- USB console connection indicator
- TX-Out
- RX-In
- UART2 - RS232 Mode
- RS232
- Carrier-board EEPROM
- RS-232
- RS-232
- 3.3V x 2mA = 6.6mW
- RS-232
- I2C slave address: 0x54..0x57
